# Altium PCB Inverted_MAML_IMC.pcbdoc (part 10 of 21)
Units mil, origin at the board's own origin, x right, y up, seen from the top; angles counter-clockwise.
Board outline 7677.1 x 6771.6 mil, 6 copper layers (Top Layer, Inner1, Inner2, Inner3, Inner4, Bottom Layer), stack 60.7 mil thick; 2732 components, 1531 nets, 7765 pads, 3705 vias.
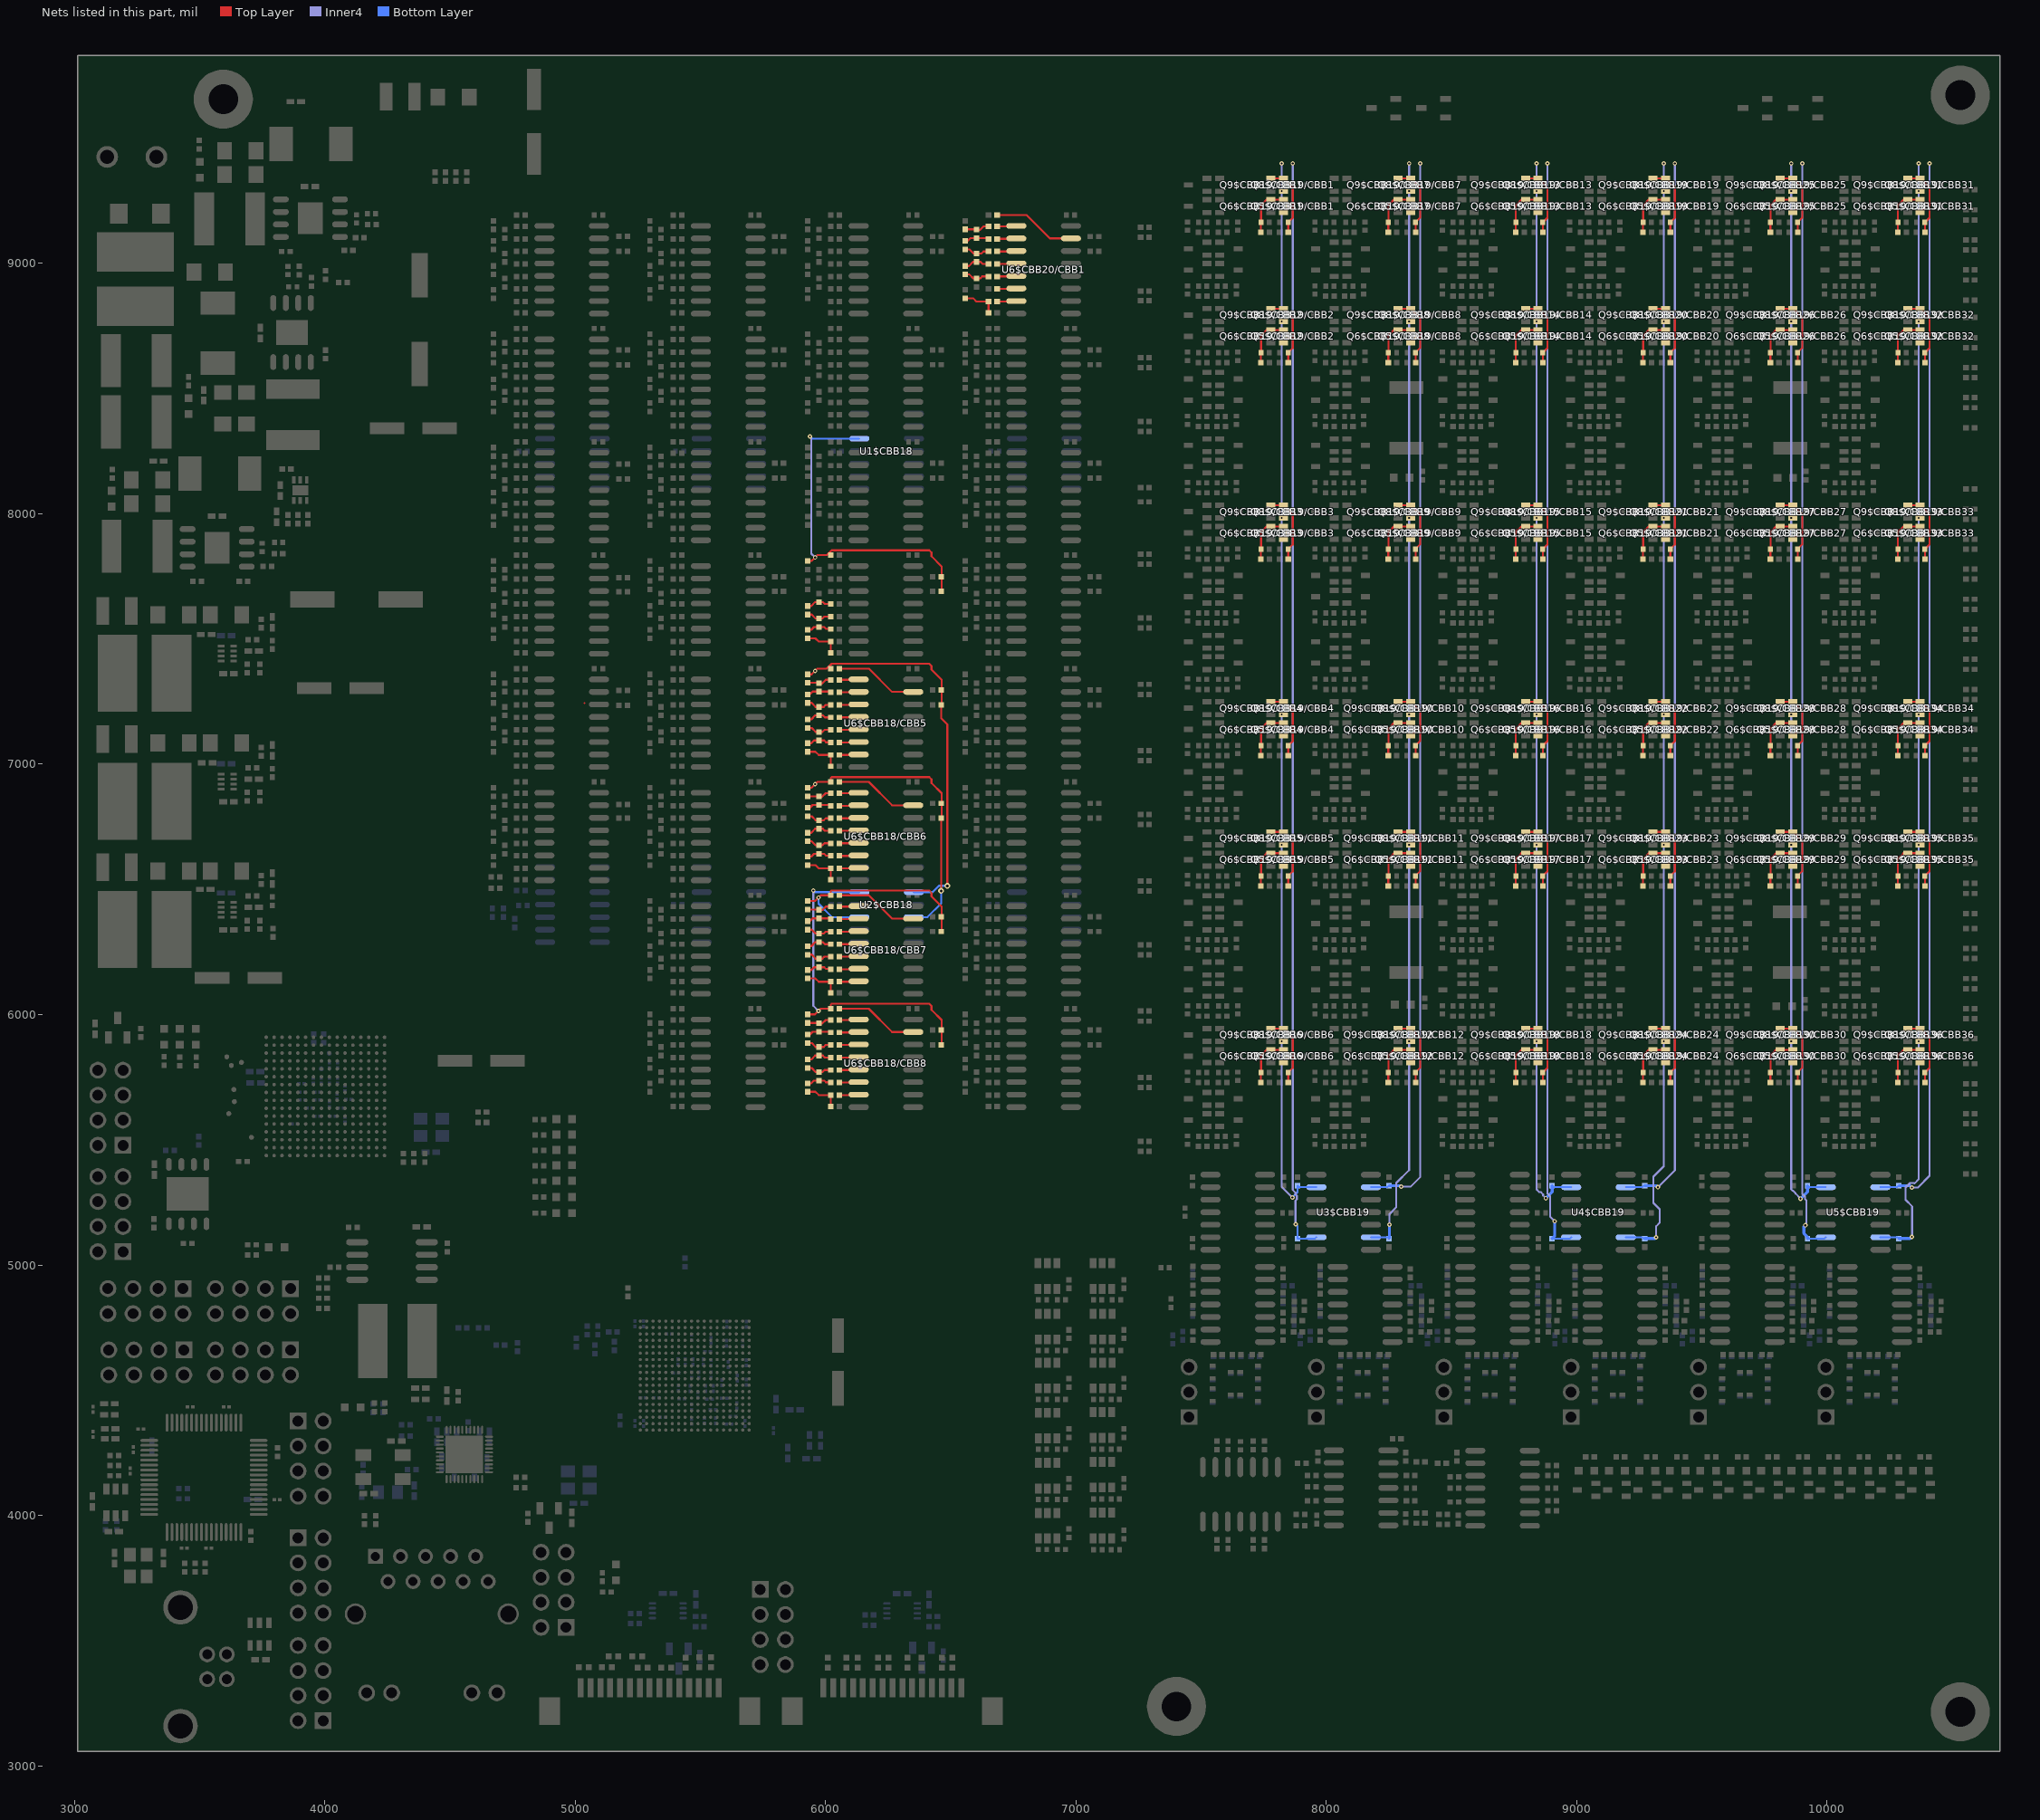
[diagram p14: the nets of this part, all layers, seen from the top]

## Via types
v1: diameter 17.7, hole 7.9, Top Layer to Bottom Layer, 3373 vias
v2: diameter 13.8, hole 7.9, Top Layer to Bottom Layer, 287 vias
v3: diameter 23.6, hole 11.8, Top Layer to Bottom Layer, 45 vias

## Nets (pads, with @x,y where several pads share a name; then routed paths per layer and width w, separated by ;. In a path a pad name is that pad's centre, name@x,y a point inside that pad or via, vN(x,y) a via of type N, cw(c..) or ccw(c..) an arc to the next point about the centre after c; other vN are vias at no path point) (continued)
$1I35\$1I23\$1N14: R4$CBB18/CBB4.2 R13$CBB18/CBB4.1 R14$CBB18/CBB4.2 | length 102.9
  Top Layer w7.9: R13$CBB18/CBB4.1@5928.7,7597.5 5945,7597.5 5960.9,7581.6 R14$CBB18/CBB4.2@5973.7,7581.6 5988.2,7581.6 5996.1,7589.6 R4$CBB18/CBB4.2@6021.7,7589.6
$1I35\$1I23\$1N15: R5$CBB18/CBB4.2 R12$CBB18/CBB4.1 R13$CBB18/CBB4.2 | length 102.8
  Top Layer w7.9: R13$CBB18/CBB4.2@5928.7,7631.6 5943.2,7631.6 5959.1,7647.5 R12$CBB18/CBB4.1@5973.7,7647.5 5990,7647.5 5998,7639.6 R5$CBB18/CBB4.2@6021.7,7639.6
$1I35\$1I23\$1N16: R1$CBB18/CBB4.2 R15$CBB18/CBB4.1 R16$CBB18/CBB4.2 | length 143.3
  Top Layer w7.9: R15$CBB18/CBB4.1@5928.7,7502.5 5960,7502.5 5973,7489.6 R1$CBB18/CBB4.2@6021.7,7489.6 R16$CBB18/CBB4.2@6021.7,7444.6
$1I35\$1I23\$1N17: R3$CBB18/CBB4.2 R14$CBB18/CBB4.1 R15$CBB18/CBB4.2 | length 100.8
  Top Layer w7.9: R15$CBB18/CBB4.2@5928.7,7536.6 5943.2,7536.6 5954.1,7547.5 R14$CBB18/CBB4.1@5973.7,7547.5 5995,7547.5 6002,7540.5 6020.8,7540.5 R3$CBB18/CBB4.2@6021.7,7539.6
$1I35\$1I23\DAC_LAD_OUT: R2$CBB18/CBB4.2 R9$CBB18/CBB4.2 R112$CBB18.1 R128$CBB18.2 U1$CBB18.12 | length 1379.4
  Top Layer w7.9: R2$CBB18/CBB4.2@5928.7,7811.6 5944.8,7811.6 v1(5958.7,7825.5) 5967.8,7834.6 6005.1,7834.6 6024.7,7854.1 6414.4,7854.1 6423.4,7845.1 6423.4,7830.1 6464.1,7789.4 R128$CBB18.2@6464.1,7690.5
  Inner4 w7.9: v1(5938.6,8308.8) 5943.5,8303.8 5943.5,7840.6 v1(5958.7,7825.5)
  Bottom Layer w7.9: v1(5938.6,8308.8) 5947.2,8300.1 U1$CBB18.12@6135.3,8300.1
$1I35\$1I33\$1N1: R9$CBB18/CBB5.1 U6$CBB18/CBB5.15 | length 333.5
  Top Layer w7.9: R9$CBB18/CBB5.1@6055.7,7381.8 6173,7381.8 6266.2,7288.6 U6$CBB18/CBB5.15@6350.6,7288.6
$1I35\$1I33\$1N2: R8$CBB18/CBB5.1 U6$CBB18/CBB5.1 | length 77.6
  Top Layer w7.9: R8$CBB18/CBB5.1@6055.7,7336.8 6130.8,7336.8 U6$CBB18/CBB5.1@6132.6,7338.6
$1I35\$1I33\$1N3: R7$CBB18/CBB5.1 U6$CBB18/CBB5.2 | length 77.6
  Top Layer w7.9: R7$CBB18/CBB5.1@6055.7,7286.8 6130.8,7286.8 U6$CBB18/CBB5.2@6132.6,7288.6
$1I35\$1I33\$1N4: R6$CBB18/CBB5.1 U6$CBB18/CBB5.3 | length 77.6
  Top Layer w7.9: R6$CBB18/CBB5.1@6055.7,7236.8 6130.8,7236.8 U6$CBB18/CBB5.3@6132.6,7238.6
$1I35\$1I33\$1N5: R5$CBB18/CBB5.1 U6$CBB18/CBB5.4 | length 77.6
  Top Layer w7.9: R5$CBB18/CBB5.1@6055.7,7186.8 6130.8,7186.8 U6$CBB18/CBB5.4@6132.6,7188.6
$1I35\$1I33\$1N6: R4$CBB18/CBB5.1 U6$CBB18/CBB5.5 | length 77.6
  Top Layer w7.9: R4$CBB18/CBB5.1@6055.7,7136.8 6130.8,7136.8 U6$CBB18/CBB5.5@6132.6,7138.6
$1I35\$1I33\$1N7: R3$CBB18/CBB5.1 U6$CBB18/CBB5.6 | length 77.6
  Top Layer w7.9: R3$CBB18/CBB5.1@6055.7,7086.8 6130.8,7086.8 U6$CBB18/CBB5.6@6132.6,7088.6
$1I35\$1I33\$1N8: R1$CBB18/CBB5.1 U6$CBB18/CBB5.7 | length 77.6
  Top Layer w7.9: R1$CBB18/CBB5.1@6055.7,7036.8 6130.8,7036.8 U6$CBB18/CBB5.7@6132.6,7038.6
$1I35\$1I33\$1N11: R2$CBB18/CBB5.1 R8$CBB18/CBB5.2 R10$CBB18/CBB5.2 | length 99.7
  Top Layer w7.9: R2$CBB18/CBB5.1@5928.7,7324.8 5972.8,7324.8 R10$CBB18/CBB5.2@5973.7,7323.8 5974.8,7322.7 5987,7322.7 6001.1,7336.8 R8$CBB18/CBB5.2@6021.7,7336.8
$1I35\$1I33\$1N12: R6$CBB18/CBB5.2 R11$CBB18/CBB5.1 R12$CBB18/CBB5.2 | length 103
  Top Layer w7.9: R11$CBB18/CBB5.1@5928.7,7244.8 5945,7244.8 5960.9,7228.8 R12$CBB18/CBB5.2@5973.7,7228.8 5993.2,7228.8 6001.1,7236.8 R6$CBB18/CBB5.2@6021.7,7236.8
$1I35\$1I33\$1N13: R7$CBB18/CBB5.2 R10$CBB18/CBB5.1 R11$CBB18/CBB5.2 | length 98.8
  Top Layer w7.9: R11$CBB18/CBB5.2@5928.7,7278.8 5938.2,7278.8 5949.1,7289.8 R10$CBB18/CBB5.1@5973.7,7289.8 6018.7,7289.8 R7$CBB18/CBB5.2@6021.7,7286.8
$1I35\$1I33\$1N14: R4$CBB18/CBB5.2 R13$CBB18/CBB5.1 R14$CBB18/CBB5.2 | length 103
  Top Layer w7.9: R13$CBB18/CBB5.1@5928.7,7144.8 5945,7144.8 5960.9,7128.8 R14$CBB18/CBB5.2@5973.7,7128.8 5988.2,7128.8 5996.1,7136.8 R4$CBB18/CBB5.2@6021.7,7136.8
$1I35\$1I33\$1N15: R5$CBB18/CBB5.2 R12$CBB18/CBB5.1 R13$CBB18/CBB5.2 | length 103
  Top Layer w7.9: R13$CBB18/CBB5.2@5928.7,7178.8 5943.2,7178.8 5959.1,7194.8 R12$CBB18/CBB5.1@5973.7,7194.8 5990,7194.8 5998,7186.8 R5$CBB18/CBB5.2@6021.7,7186.8
$1I35\$1I33\$1N16: R1$CBB18/CBB5.2 R15$CBB18/CBB5.1 R16$CBB18/CBB5.2 | length 143.4
  Top Layer w7.9: R15$CBB18/CBB5.1@5928.7,7049.8 5960,7049.8 5973,7036.8 R1$CBB18/CBB5.2@6021.7,7036.8 R16$CBB18/CBB5.2@6021.7,6991.8
$1I35\$1I33\$1N17: R3$CBB18/CBB5.2 R14$CBB18/CBB5.1 R15$CBB18/CBB5.2 | length 100.9
  Top Layer w7.9: R15$CBB18/CBB5.2@5928.7,7083.8 5943.2,7083.8 5954.1,7094.8 R14$CBB18/CBB5.1@5973.7,7094.8 5995,7094.8 6002,7087.7 6020.8,7087.7 R3$CBB18/CBB5.2@6021.7,7086.8
$1I35\$1I33\DAC_LAD_OUT: R2$CBB18/CBB5.2 R9$CBB18/CBB5.2 R129$CBB18.1 R130$CBB18.2 U2$CBB18.3 | length 1566.2
  Top Layer w7.9: R2$CBB18/CBB5.2@5928.7,7358.8 5944.8,7358.8 v1(5958.7,7372.7) 5967.8,7381.8 6005.1,7381.8 6024.7,7401.4 6414.4,7401.4 6423.4,7392.4 6423.4,7377.4 6464.1,7336.7 R130$CBB18.2@6464.1,7237.7 ; R130$CBB18.2@6461.9,7237.1 6462.1,7236.9 6462.1,7183.7 6487.1,7158.7 v3(6487.1,6513.7)
  Bottom Layer w7.9: U2$CBB18.3@6353.3,6489.1 6428.1,6489.1 6453.5,6514.5 6486.4,6514.5 v3(6487.1,6513.7)
$1I35\$1I34\$1N1: R9$CBB18/CBB6.1 U6$CBB18/CBB6.15 | length 333.5
  Top Layer w7.9: R9$CBB18/CBB6.1@6055.7,6929 6173,6929 6266.2,6835.8 U6$CBB18/CBB6.15@6350.6,6835.8
$1I35\$1I34\$1N2: R8$CBB18/CBB6.1 U6$CBB18/CBB6.1 | length 77.6
  Top Layer w7.9: R8$CBB18/CBB6.1@6055.7,6884 6130.8,6884 U6$CBB18/CBB6.1@6132.6,6885.8
$1I35\$1I34\$1N3: R7$CBB18/CBB6.1 U6$CBB18/CBB6.2 | length 77.6
  Top Layer w7.9: R7$CBB18/CBB6.1@6055.7,6834 6130.8,6834 U6$CBB18/CBB6.2@6132.6,6835.8
$1I35\$1I34\$1N4: R6$CBB18/CBB6.1 U6$CBB18/CBB6.3 | length 77.6
  Top Layer w7.9: R6$CBB18/CBB6.1@6055.7,6784 6130.8,6784 U6$CBB18/CBB6.3@6132.6,6785.8
$1I35\$1I34\$1N5: R5$CBB18/CBB6.1 U6$CBB18/CBB6.4 | length 77.6
  Top Layer w7.9: R5$CBB18/CBB6.1@6055.7,6734 6130.8,6734 U6$CBB18/CBB6.4@6132.6,6735.8
$1I35\$1I34\$1N6: R4$CBB18/CBB6.1 U6$CBB18/CBB6.5 | length 77.6
  Top Layer w7.9: R4$CBB18/CBB6.1@6055.7,6684 6130.8,6684 U6$CBB18/CBB6.5@6132.6,6685.8
$1I35\$1I34\$1N7: R3$CBB18/CBB6.1 U6$CBB18/CBB6.6 | length 77.6
  Top Layer w7.9: R3$CBB18/CBB6.1@6055.7,6634 6130.8,6634 U6$CBB18/CBB6.6@6132.6,6635.8
$1I35\$1I34\$1N8: R1$CBB18/CBB6.1 U6$CBB18/CBB6.7 | length 77.6
  Top Layer w7.9: R1$CBB18/CBB6.1@6055.7,6584 6130.8,6584 U6$CBB18/CBB6.7@6132.6,6585.8
$1I35\$1I34\$1N11: R2$CBB18/CBB6.1 R8$CBB18/CBB6.2 R10$CBB18/CBB6.2 | length 99.6
  Top Layer w7.9: R2$CBB18/CBB6.1@5928.7,6872 5972.8,6872 R10$CBB18/CBB6.2@5973.7,6871.1 5974.8,6870 5987,6870 6001.1,6884 R8$CBB18/CBB6.2@6021.7,6884
$1I35\$1I34\$1N12: R6$CBB18/CBB6.2 R11$CBB18/CBB6.1 R12$CBB18/CBB6.2 | length 102.9
  Top Layer w7.9: R11$CBB18/CBB6.1@5928.7,6792 5945,6792 5960.9,6776.1 R12$CBB18/CBB6.2@5973.7,6776.1 5993.2,6776.1 6001.1,6784 R6$CBB18/CBB6.2@6021.7,6784
$1I35\$1I34\$1N13: R7$CBB18/CBB6.2 R10$CBB18/CBB6.1 R11$CBB18/CBB6.2 | length 98.8
  Top Layer w7.9: R11$CBB18/CBB6.2@5928.7,6826.1 5938.2,6826.1 5949.1,6837 R10$CBB18/CBB6.1@5973.7,6837 6018.7,6837 R7$CBB18/CBB6.2@6021.7,6834
$1I35\$1I34\$1N14: R4$CBB18/CBB6.2 R13$CBB18/CBB6.1 R14$CBB18/CBB6.2 | length 102.9
  Top Layer w7.9: R13$CBB18/CBB6.1@5928.7,6692 5945,6692 5960.9,6676.1 R14$CBB18/CBB6.2@5973.7,6676.1 5988.2,6676.1 5996.1,6684 R4$CBB18/CBB6.2@6021.7,6684
$1I35\$1I34\$1N15: R5$CBB18/CBB6.2 R12$CBB18/CBB6.1 R13$CBB18/CBB6.2 | length 102.9
  Top Layer w7.9: R13$CBB18/CBB6.2@5928.7,6726.1 5943.2,6726.1 5959.1,6742 R12$CBB18/CBB6.1@5973.7,6742 5990,6742 5998,6734 R5$CBB18/CBB6.2@6021.7,6734
$1I35\$1I34\$1N16: R1$CBB18/CBB6.2 R15$CBB18/CBB6.1 R16$CBB18/CBB6.2 | length 143.4
  Top Layer w7.9: R15$CBB18/CBB6.1@5928.7,6597 5960,6597 5973,6584 R1$CBB18/CBB6.2@6021.7,6584 R16$CBB18/CBB6.2@6021.7,6539
$1I35\$1I34\$1N17: R3$CBB18/CBB6.2 R14$CBB18/CBB6.1 R15$CBB18/CBB6.2 | length 100.9
  Top Layer w7.9: R15$CBB18/CBB6.2@5928.7,6631.1 5943.2,6631.1 5954.1,6642 R14$CBB18/CBB6.1@5973.7,6642 5995,6642 6002,6635 6020.8,6635 R3$CBB18/CBB6.2@6021.7,6634
$1I35\$1I34\DAC_LAD_OUT: R2$CBB18/CBB6.2 R9$CBB18/CBB6.2 R131$CBB18.1 R132$CBB18.2 U2$CBB18.5 | length 1169.4
  Top Layer w7.9: R2$CBB18/CBB6.2@5928.7,6906.1 5944.8,6906.1 v1(5958.7,6920) 5967.8,6929 R9$CBB18/CBB6.2@6021.7,6929 6021.7,6945.6 6024.7,6948.6 6414.4,6948.6 6423.4,6939.6 6423.4,6924.6 6464.1,6883.9 R132$CBB18.2@6464.1,6785 ; R132$CBB18.2@6461.9,6784.4 6461.9,6493.9 v3(6462.1,6493.7)
  Bottom Layer w7.9: U2$CBB18.5@6353.3,6389.1 6407.5,6389.1 6462.1,6443.7 v3(6462.1,6493.7)
$1I35\$1I35\$1N1: R9$CBB18/CBB7.1 U6$CBB18/CBB7.15 | length 333.5
  Top Layer w7.9: R9$CBB18/CBB7.1@6055.7,6476.3 6173,6476.3 6266.2,6383.1 U6$CBB18/CBB7.15@6350.6,6383.1
$1I35\$1I35\$1N2: R8$CBB18/CBB7.1 U6$CBB18/CBB7.1 | length 77.6
  Top Layer w7.9: R8$CBB18/CBB7.1@6055.7,6431.3 6130.8,6431.3 U6$CBB18/CBB7.1@6132.6,6433.1
$1I35\$1I35\$1N3: R7$CBB18/CBB7.1 U6$CBB18/CBB7.2 | length 77.6
  Top Layer w7.9: R7$CBB18/CBB7.1@6055.7,6381.3 6130.8,6381.3 U6$CBB18/CBB7.2@6132.6,6383.1
$1I35\$1I35\$1N4: R6$CBB18/CBB7.1 U6$CBB18/CBB7.3 | length 77.6
  Top Layer w7.9: R6$CBB18/CBB7.1@6055.7,6331.3 6130.8,6331.3 U6$CBB18/CBB7.3@6132.6,6333.1
$1I35\$1I35\$1N5: R5$CBB18/CBB7.1 U6$CBB18/CBB7.4 | length 77.6
  Top Layer w7.9: R5$CBB18/CBB7.1@6055.7,6281.3 6130.8,6281.3 U6$CBB18/CBB7.4@6132.6,6283.1
$1I35\$1I35\$1N6: R4$CBB18/CBB7.1 U6$CBB18/CBB7.5 | length 77.6
  Top Layer w7.9: R4$CBB18/CBB7.1@6055.7,6231.3 6130.8,6231.3 U6$CBB18/CBB7.5@6132.6,6233.1
$1I35\$1I35\$1N7: R3$CBB18/CBB7.1 U6$CBB18/CBB7.6 | length 77.6
  Top Layer w7.9: R3$CBB18/CBB7.1@6055.7,6181.3 6130.8,6181.3 U6$CBB18/CBB7.6@6132.6,6183.1
$1I35\$1I35\$1N8: R1$CBB18/CBB7.1 U6$CBB18/CBB7.7 | length 77.6
  Top Layer w7.9: R1$CBB18/CBB7.1@6055.7,6131.3 6130.8,6131.3 U6$CBB18/CBB7.7@6132.6,6133.1
$1I35\$1I35\$1N11: R2$CBB18/CBB7.1 R8$CBB18/CBB7.2 R10$CBB18/CBB7.2 | length 99.7
  Top Layer w7.9: R2$CBB18/CBB7.1@5928.7,6419.2 5972.8,6419.2 R10$CBB18/CBB7.2@5973.7,6418.3 5974.8,6417.2 5987,6417.2 6001.1,6431.3 R8$CBB18/CBB7.2@6021.7,6431.3
$1I35\$1I35\$1N12: R6$CBB18/CBB7.2 R11$CBB18/CBB7.1 R12$CBB18/CBB7.2 | length 102.9
  Top Layer w7.9: R11$CBB18/CBB7.1@5928.7,6339.2 5945,6339.2 5960.9,6323.3 R12$CBB18/CBB7.2@5973.7,6323.3 5993.2,6323.3 6001.1,6331.3 R6$CBB18/CBB7.2@6021.7,6331.3
$1I35\$1I35\$1N13: R7$CBB18/CBB7.2 R10$CBB18/CBB7.1 R11$CBB18/CBB7.2 | length 98.7
  Top Layer w7.9: R11$CBB18/CBB7.2@5928.7,6373.3 5938.2,6373.3 5949.1,6384.2 R10$CBB18/CBB7.1@5973.7,6384.2 6018.7,6384.2 R7$CBB18/CBB7.2@6021.7,6381.3
$1I35\$1I35\$1N14: R4$CBB18/CBB7.2 R13$CBB18/CBB7.1 R14$CBB18/CBB7.2 | length 102.9
  Top Layer w7.9: R13$CBB18/CBB7.1@5928.7,6239.2 5945,6239.2 5960.9,6223.3 R14$CBB18/CBB7.2@5973.7,6223.3 5988.2,6223.3 5996.1,6231.3 R4$CBB18/CBB7.2@6021.7,6231.3
$1I35\$1I35\$1N15: R5$CBB18/CBB7.2 R12$CBB18/CBB7.1 R13$CBB18/CBB7.2 | length 102.8
  Top Layer w7.9: R13$CBB18/CBB7.2@5928.7,6273.3 5943.2,6273.3 5959.1,6289.2 R12$CBB18/CBB7.1@5973.7,6289.2 5990,6289.2 5998,6281.3 R5$CBB18/CBB7.2@6021.7,6281.3
$1I35\$1I35\$1N16: R1$CBB18/CBB7.2 R15$CBB18/CBB7.1 R16$CBB18/CBB7.2 | length 143.3
  Top Layer w7.9: R15$CBB18/CBB7.1@5928.7,6144.2 5960,6144.2 5973,6131.3 R1$CBB18/CBB7.2@6021.7,6131.3 R16$CBB18/CBB7.2@6021.7,6086.3
$1I35\$1I35\$1N17: R3$CBB18/CBB7.2 R14$CBB18/CBB7.1 R15$CBB18/CBB7.2 | length 100.8
  Top Layer w7.9: R15$CBB18/CBB7.2@5928.7,6178.3 5943.2,6178.3 5954.1,6189.2 R14$CBB18/CBB7.1@5973.7,6189.2 5995,6189.2 6002,6182.2 6020.8,6182.2 R3$CBB18/CBB7.2@6021.7,6181.3
$1I35\$1I35\DAC_LAD_OUT: R2$CBB18/CBB7.2 R9$CBB18/CBB7.2 R133$CBB18.1 R134$CBB18.2 U2$CBB18.10 | length 907.3
  Top Layer w7.9: R2$CBB18/CBB7.2@5928.7,6453.3 5958.2,6453.3 v1(5972,6467.2) 5981.1,6476.3 R9$CBB18/CBB7.2@6021.7,6476.3 6021.7,6492.8 6024.7,6495.9 6414.4,6495.9 6423.4,6486.9 6423.4,6471.9 6464.1,6431.2 R134$CBB18.2@6464.1,6332.2
  Bottom Layer w7.9: v1@5972.1,6467.2 5972.1,6442.7 6025.7,6389.1 U2$CBB18.10@6135.3,6389.1
$1I35\$1I36\$1N1: R9$CBB18/CBB8.1 U6$CBB18/CBB8.15 | length 333.5
  Top Layer w7.9: R9$CBB18/CBB8.1@6055.7,6023.5 6173,6023.5 6266.2,5930.3 U6$CBB18/CBB8.15@6350.6,5930.3
$1I35\$1I36\$1N2: R8$CBB18/CBB8.1 U6$CBB18/CBB8.1 | length 77.6
  Top Layer w7.9: R8$CBB18/CBB8.1@6055.7,5978.5 6130.8,5978.5 U6$CBB18/CBB8.1@6132.6,5980.3
$1I35\$1I36\$1N3: R7$CBB18/CBB8.1 U6$CBB18/CBB8.2 | length 77.6
  Top Layer w7.9: R7$CBB18/CBB8.1@6055.7,5928.5 6130.8,5928.5 U6$CBB18/CBB8.2@6132.6,5930.3
$1I35\$1I36\$1N4: R6$CBB18/CBB8.1 U6$CBB18/CBB8.3 | length 77.6
  Top Layer w7.9: R6$CBB18/CBB8.1@6055.7,5878.5 6130.8,5878.5 U6$CBB18/CBB8.3@6132.6,5880.3
$1I35\$1I36\$1N5: R5$CBB18/CBB8.1 U6$CBB18/CBB8.4 | length 77.6
  Top Layer w7.9: R5$CBB18/CBB8.1@6055.7,5828.5 6130.8,5828.5 U6$CBB18/CBB8.4@6132.6,5830.3
$1I35\$1I36\$1N6: R4$CBB18/CBB8.1 U6$CBB18/CBB8.5 | length 77.6
  Top Layer w7.9: R4$CBB18/CBB8.1@6055.7,5778.5 6130.8,5778.5 U6$CBB18/CBB8.5@6132.6,5780.3
$1I35\$1I36\$1N7: R3$CBB18/CBB8.1 U6$CBB18/CBB8.6 | length 77.6
  Top Layer w7.9: R3$CBB18/CBB8.1@6055.7,5728.5 6130.8,5728.5 U6$CBB18/CBB8.6@6132.6,5730.3
$1I35\$1I36\$1N8: R1$CBB18/CBB8.1 U6$CBB18/CBB8.7 | length 77.6
  Top Layer w7.9: R1$CBB18/CBB8.1@6055.7,5678.5 6130.8,5678.5 U6$CBB18/CBB8.7@6132.6,5680.3
$1I35\$1I36\$1N11: R2$CBB18/CBB8.1 R8$CBB18/CBB8.2 R10$CBB18/CBB8.2 | length 99.7
  Top Layer w7.9: R2$CBB18/CBB8.1@5928.7,5966.5 5972.8,5966.5 R10$CBB18/CBB8.2@5973.7,5965.6 5974.8,5964.4 5987,5964.4 6001.1,5978.5 R8$CBB18/CBB8.2@6021.7,5978.5
$1I35\$1I36\$1N12: R6$CBB18/CBB8.2 R11$CBB18/CBB8.1 R12$CBB18/CBB8.2 | length 102.9
  Top Layer w7.9: R11$CBB18/CBB8.1@5928.7,5886.5 5945,5886.5 5960.9,5870.6 R12$CBB18/CBB8.2@5973.7,5870.6 5993.2,5870.6 6001.1,5878.5 R6$CBB18/CBB8.2@6021.7,5878.5
$1I35\$1I36\$1N13: R7$CBB18/CBB8.2 R10$CBB18/CBB8.1 R11$CBB18/CBB8.2 | length 98.8
  Top Layer w7.9: R11$CBB18/CBB8.2@5928.7,5920.6 5938.2,5920.6 5949.1,5931.5 R10$CBB18/CBB8.1@5973.7,5931.5 6018.7,5931.5 R7$CBB18/CBB8.2@6021.7,5928.5
$1I35\$1I36\$1N14: R4$CBB18/CBB8.2 R13$CBB18/CBB8.1 R14$CBB18/CBB8.2 | length 102.9
  Top Layer w7.9: R13$CBB18/CBB8.1@5928.7,5786.5 5945,5786.5 5960.9,5770.6 R14$CBB18/CBB8.2@5973.7,5770.6 5988.2,5770.6 5996.1,5778.5 R4$CBB18/CBB8.2@6021.7,5778.5
$1I35\$1I36\$1N15: R5$CBB18/CBB8.2 R12$CBB18/CBB8.1 R13$CBB18/CBB8.2 | length 102.9
  Top Layer w7.9: R13$CBB18/CBB8.2@5928.7,5820.6 5943.2,5820.6 5959.1,5836.5 R12$CBB18/CBB8.1@5973.7,5836.5 5990,5836.5 5998,5828.5 R5$CBB18/CBB8.2@6021.7,5828.5
$1I35\$1I36\$1N16: R1$CBB18/CBB8.2 R15$CBB18/CBB8.1 R16$CBB18/CBB8.2 | length 143.4
  Top Layer w7.9: R15$CBB18/CBB8.1@5928.7,5691.5 5960,5691.5 5973,5678.5 R1$CBB18/CBB8.2@6021.7,5678.5 R16$CBB18/CBB8.2@6021.7,5633.5
$1I35\$1I36\$1N17: R3$CBB18/CBB8.2 R14$CBB18/CBB8.1 R15$CBB18/CBB8.2 | length 100.9
  Top Layer w7.9: R15$CBB18/CBB8.2@5928.7,5725.6 5943.2,5725.6 5954.1,5736.5 R14$CBB18/CBB8.1@5973.7,5736.5 5995,5736.5 6002,5729.4 6020.8,5729.4 R3$CBB18/CBB8.2@6021.7,5728.5
$1I35\$1I36\DAC_LAD_OUT: R2$CBB18/CBB8.2 R9$CBB18/CBB8.2 R135$CBB18.1 R136$CBB18.2 U2$CBB18.12 | length 1373
  Top Layer w7.9: R2$CBB18/CBB8.2@5928.7,6000.6 5958.2,6000.6 v1(5972,6014.4) 5981.1,6023.5 R9$CBB18/CBB8.2@6021.7,6023.5 6021.7,6040.1 6024.7,6043.1 6414.4,6043.1 6423.4,6034.1 6423.4,6019.1 6464.1,5978.4 R136$CBB18.2@6464.1,5879.4
  Inner4 w7.9: v1(5951.7,6495.5) 5951.7,6034.8 v1(5972,6014.4)
  Bottom Layer w7.9: v1(5951.7,6495.5) 5958.1,6489.1 U2$CBB18.12@6135.3,6489.1
$1I36\$1I263\$2N1: C1$CBB19/CBB1.2 Q5$CBB19/CBB1.1 Q6$CBB19/CBB1.2 R1$CBB19/CBB1.2 | length 207
  Top Layer w7.9: R1$CBB19/CBB1.2@7739.1,9123.7 7739.1,9163.2 C1$CBB19/CBB1.2@7739.6,9163.7 7739.6,9232.2 7761.8,9254.3 Q6$CBB19/CBB1.2@7778.6,9254.3 Q5$CBB19/CBB1.1@7828.8,9254.3
$1I36\$1I263\$2N14: C3$CBB19/CBB1.2 Q8$CBB19/CBB1.1 Q9$CBB19/CBB1.2 R2$CBB19/CBB1.2 | length 289.2
  Top Layer w7.9: Q9$CBB19/CBB1.2@7778.6,9339.3 Q8$CBB19/CBB1.1@7828.8,9339.3 7866.2,9301.9 7866.2,9182.2 C3$CBB19/CBB1.2@7847.7,9163.7 7848.2,9163.2 R2$CBB19/CBB1.2@7848.2,9123.7
$1I36\$1I265\$2N1: C1$CBB19/CBB3.2 Q5$CBB19/CBB3.1 Q6$CBB19/CBB3.2 R1$CBB19/CBB3.2 | length 207
  Top Layer w7.9: R1$CBB19/CBB3.2@7739.1,7818.7 7739.1,7858.2 C1$CBB19/CBB3.2@7739.6,7858.7 7739.6,7927.2 7761.8,7949.3 Q6$CBB19/CBB3.2@7778.6,7949.3 Q5$CBB19/CBB3.1@7828.8,7949.3
$1I36\$1I265\$2N14: C3$CBB19/CBB3.2 Q8$CBB19/CBB3.1 Q9$CBB19/CBB3.2 R2$CBB19/CBB3.2 | length 289.2
  Top Layer w7.9: Q9$CBB19/CBB3.2@7778.6,8034.3 Q8$CBB19/CBB3.1@7828.8,8034.3 7866.2,7996.9 7866.2,7877.2 C3$CBB19/CBB3.2@7847.7,7858.7 7848.2,7858.2 R2$CBB19/CBB3.2@7848.2,7818.7
$1I36\$1I267\$2N1: C1$CBB19/CBB5.2 Q5$CBB19/CBB5.1 Q6$CBB19/CBB5.2 R1$CBB19/CBB5.2 | length 207
  Top Layer w7.9: R1$CBB19/CBB5.2@7739.1,6513.7 7739.1,6553.2 C1$CBB19/CBB5.2@7739.6,6553.7 7739.6,6622.2 7761.8,6644.3 Q6$CBB19/CBB5.2@7778.6,6644.3 Q5$CBB19/CBB5.1@7828.8,6644.3
$1I36\$1I267\$2N14: C3$CBB19/CBB5.2 Q8$CBB19/CBB5.1 Q9$CBB19/CBB5.2 R2$CBB19/CBB5.2 | length 289.2
  Top Layer w7.9: Q9$CBB19/CBB5.2@7778.6,6729.3 Q8$CBB19/CBB5.1@7828.8,6729.3 7866.2,6691.9 7866.2,6572.2 C3$CBB19/CBB5.2@7847.7,6553.7 7848.2,6553.2 R2$CBB19/CBB5.2@7848.2,6513.7
$1I36\$1I269\$2N1: C1$CBB19/CBB7.2 Q5$CBB19/CBB7.1 Q6$CBB19/CBB7.2 R1$CBB19/CBB7.2 | length 207
  Top Layer w7.9: R1$CBB19/CBB7.2@8247.8,9123.7 8247.8,9163.2 C1$CBB19/CBB7.2@8248.3,9163.7 8248.3,9232.2 8270.5,9254.3 Q6$CBB19/CBB7.2@8287.3,9254.3 Q5$CBB19/CBB7.1@8337.5,9254.3
$1I36\$1I269\$2N14: C3$CBB19/CBB7.2 Q8$CBB19/CBB7.1 Q9$CBB19/CBB7.2 R2$CBB19/CBB7.2 | length 289.2
  Top Layer w7.9: Q9$CBB19/CBB7.2@8287.3,9339.3 Q8$CBB19/CBB7.1@8337.5,9339.3 8374.9,9301.9 8374.9,9182.2 C3$CBB19/CBB7.2@8356.4,9163.7 8356.9,9163.2 R2$CBB19/CBB7.2@8356.9,9123.7
$1I36\$1I270\$2N1: C1$CBB19/CBB8.2 Q5$CBB19/CBB8.1 Q6$CBB19/CBB8.2 R1$CBB19/CBB8.2 | length 207
  Top Layer w7.9: R1$CBB19/CBB8.2@8247.8,8603.7 8247.8,8643.2 C1$CBB19/CBB8.2@8248.3,8643.7 8248.3,8712.2 8270.5,8734.3 Q6$CBB19/CBB8.2@8287.3,8734.3 Q5$CBB19/CBB8.1@8337.5,8734.3
$1I36\$1I270\$2N14: C3$CBB19/CBB8.2 Q8$CBB19/CBB8.1 Q9$CBB19/CBB8.2 R2$CBB19/CBB8.2 | length 289.2
  Top Layer w7.9: Q9$CBB19/CBB8.2@8287.3,8819.3 Q8$CBB19/CBB8.1@8337.5,8819.3 8374.9,8781.9 8374.9,8662.2 C3$CBB19/CBB8.2@8356.4,8643.7 8356.9,8643.2 R2$CBB19/CBB8.2@8356.9,8603.7
$1I36\$1I271\$2N1: C1$CBB19/CBB9.2 Q5$CBB19/CBB9.1 Q6$CBB19/CBB9.2 R1$CBB19/CBB9.2 | length 207
  Top Layer w7.9: R1$CBB19/CBB9.2@8247.8,7818.7 8247.8,7858.2 C1$CBB19/CBB9.2@8248.3,7858.7 8248.3,7927.2 8270.5,7949.3 Q6$CBB19/CBB9.2@8287.3,7949.3 Q5$CBB19/CBB9.1@8337.5,7949.3
$1I36\$1I271\$2N14: C3$CBB19/CBB9.2 Q8$CBB19/CBB9.1 Q9$CBB19/CBB9.2 R2$CBB19/CBB9.2 | length 289.2
  Top Layer w7.9: Q9$CBB19/CBB9.2@8287.3,8034.3 Q8$CBB19/CBB9.1@8337.5,8034.3 8374.9,7996.9 8374.9,7877.2 C3$CBB19/CBB9.2@8356.4,7858.7 8356.9,7858.2 R2$CBB19/CBB9.2@8356.9,7818.7
$1I36\$1I272\$2N1: C1$CBB19/CBB10.2 Q5$CBB19/CBB10.1 Q6$CBB19/CBB10.2 R1$CBB19/CBB10.2 | length 207
  Top Layer w7.9: R1$CBB19/CBB10.2@8247.8,7033.7 8247.8,7073.2 C1$CBB19/CBB10.2@8248.3,7073.7 8248.3,7142.2 8270.5,7164.3 Q6$CBB19/CBB10.2@8287.3,7164.3 Q5$CBB19/CBB10.1@8337.5,7164.3
$1I36\$1I272\$2N14: C3$CBB19/CBB10.2 Q8$CBB19/CBB10.1 Q9$CBB19/CBB10.2 R2$CBB19/CBB10.2 | length 289.2
  Top Layer w7.9: Q9$CBB19/CBB10.2@8287.3,7249.3 Q8$CBB19/CBB10.1@8337.5,7249.3 8374.9,7211.9 8374.9,7092.2 C3$CBB19/CBB10.2@8356.4,7073.7 8356.9,7073.2 R2$CBB19/CBB10.2@8356.9,7033.7
$1I36\$1I273\$2N1: C1$CBB19/CBB11.2 Q5$CBB19/CBB11.1 Q6$CBB19/CBB11.2 R1$CBB19/CBB11.2 | length 207
  Top Layer w7.9: R1$CBB19/CBB11.2@8247.8,6513.7 8247.8,6553.2 C1$CBB19/CBB11.2@8248.3,6553.7 8248.3,6622.2 8270.5,6644.3 Q6$CBB19/CBB11.2@8287.3,6644.3 Q5$CBB19/CBB11.1@8337.5,6644.3
$1I36\$1I273\$2N14: C3$CBB19/CBB11.2 Q8$CBB19/CBB11.1 Q9$CBB19/CBB11.2 R2$CBB19/CBB11.2 | length 289.2
  Top Layer w7.9: Q9$CBB19/CBB11.2@8287.3,6729.3 Q8$CBB19/CBB11.1@8337.5,6729.3 8374.9,6691.9 8374.9,6572.2 C3$CBB19/CBB11.2@8356.4,6553.7 8356.9,6553.2 R2$CBB19/CBB11.2@8356.9,6513.7
$1I36\$1I274\$2N1: C1$CBB19/CBB12.2 Q5$CBB19/CBB12.1 Q6$CBB19/CBB12.2 R1$CBB19/CBB12.2 | length 207
  Top Layer w7.9: R1$CBB19/CBB12.2@8247.8,5728.7 8247.8,5768.2 C1$CBB19/CBB12.2@8248.3,5768.7 8248.3,5837.2 8270.5,5859.3 Q6$CBB19/CBB12.2@8287.3,5859.3 Q5$CBB19/CBB12.1@8337.5,5859.3
$1I36\$1I274\$2N14: C3$CBB19/CBB12.2 Q8$CBB19/CBB12.1 Q9$CBB19/CBB12.2 R2$CBB19/CBB12.2 | length 289.2
  Top Layer w7.9: Q9$CBB19/CBB12.2@8287.3,5944.3 Q8$CBB19/CBB12.1@8337.5,5944.3 8374.9,5906.9 8374.9,5787.2 C3$CBB19/CBB12.2@8356.4,5768.7 8356.9,5768.2 R2$CBB19/CBB12.2@8356.9,5728.7
$1I36\$1I275\$2N1: C1$CBB19/CBB13.2 Q5$CBB19/CBB13.1 Q6$CBB19/CBB13.2 R1$CBB19/CBB13.2 | length 207
  Top Layer w7.9: R1$CBB19/CBB13.2@8756.5,9123.7 8756.5,9163.2 C1$CBB19/CBB13.2@8757,9163.7 8757,9232.2 8779.2,9254.3 Q6$CBB19/CBB13.2@8796,9254.3 Q5$CBB19/CBB13.1@8846.2,9254.3
$1I36\$1I275\$2N14: C3$CBB19/CBB13.2 Q8$CBB19/CBB13.1 Q9$CBB19/CBB13.2 R2$CBB19/CBB13.2 | length 289.2
  Top Layer w7.9: Q9$CBB19/CBB13.2@8796,9339.3 Q8$CBB19/CBB13.1@8846.2,9339.3 8883.6,9301.9 8883.6,9182.2 C3$CBB19/CBB13.2@8865.1,9163.7 8865.6,9163.2 R2$CBB19/CBB13.2@8865.6,9123.7
$1I36\$1I276\$2N1: C1$CBB19/CBB14.2 Q5$CBB19/CBB14.1 Q6$CBB19/CBB14.2 R1$CBB19/CBB14.2 | length 207
  Top Layer w7.9: R1$CBB19/CBB14.2@8756.5,8603.7 8756.5,8643.2 C1$CBB19/CBB14.2@8757,8643.7 8757,8712.2 8779.2,8734.3 Q6$CBB19/CBB14.2@8796,8734.3 Q5$CBB19/CBB14.1@8846.2,8734.3
$1I36\$1I276\$2N14: C3$CBB19/CBB14.2 Q8$CBB19/CBB14.1 Q9$CBB19/CBB14.2 R2$CBB19/CBB14.2 | length 289.2
  Top Layer w7.9: Q9$CBB19/CBB14.2@8796,8819.3 Q8$CBB19/CBB14.1@8846.2,8819.3 8883.6,8781.9 8883.6,8662.2 C3$CBB19/CBB14.2@8865.1,8643.7 8865.6,8643.2 R2$CBB19/CBB14.2@8865.6,8603.7
$1I36\$1I277\$2N1: C1$CBB19/CBB15.2 Q5$CBB19/CBB15.1 Q6$CBB19/CBB15.2 R1$CBB19/CBB15.2 | length 207
  Top Layer w7.9: R1$CBB19/CBB15.2@8756.5,7818.7 8756.5,7858.2 C1$CBB19/CBB15.2@8757,7858.7 8757,7927.2 8779.2,7949.3 Q6$CBB19/CBB15.2@8796,7949.3 Q5$CBB19/CBB15.1@8846.2,7949.3
$1I36\$1I277\$2N14: C3$CBB19/CBB15.2 Q8$CBB19/CBB15.1 Q9$CBB19/CBB15.2 R2$CBB19/CBB15.2 | length 289.2
  Top Layer w7.9: Q9$CBB19/CBB15.2@8796,8034.3 Q8$CBB19/CBB15.1@8846.2,8034.3 8883.6,7996.9 8883.6,7877.2 C3$CBB19/CBB15.2@8865.1,7858.7 8865.6,7858.2 R2$CBB19/CBB15.2@8865.6,7818.7
$1I36\$1I278\$2N1: C1$CBB19/CBB16.2 Q5$CBB19/CBB16.1 Q6$CBB19/CBB16.2 R1$CBB19/CBB16.2 | length 207
  Top Layer w7.9: R1$CBB19/CBB16.2@8756.5,7033.7 8756.5,7073.2 C1$CBB19/CBB16.2@8757,7073.7 8757,7142.2 8779.2,7164.3 Q6$CBB19/CBB16.2@8796,7164.3 Q5$CBB19/CBB16.1@8846.2,7164.3
$1I36\$1I278\$2N14: C3$CBB19/CBB16.2 Q8$CBB19/CBB16.1 Q9$CBB19/CBB16.2 R2$CBB19/CBB16.2 | length 289.2
  Top Layer w7.9: Q9$CBB19/CBB16.2@8796,7249.3 Q8$CBB19/CBB16.1@8846.2,7249.3 8883.6,7211.9 8883.6,7092.2 C3$CBB19/CBB16.2@8865.1,7073.7 8865.6,7073.2 R2$CBB19/CBB16.2@8865.6,7033.7
$1I36\$1I279\$2N1: C1$CBB19/CBB17.2 Q5$CBB19/CBB17.1 Q6$CBB19/CBB17.2 R1$CBB19/CBB17.2 | length 207
  Top Layer w7.9: R1$CBB19/CBB17.2@8756.5,6513.7 8756.5,6553.2 C1$CBB19/CBB17.2@8757,6553.7 8757,6622.2 8779.2,6644.3 Q6$CBB19/CBB17.2@8796,6644.3 Q5$CBB19/CBB17.1@8846.2,6644.3
$1I36\$1I279\$2N14: C3$CBB19/CBB17.2 Q8$CBB19/CBB17.1 Q9$CBB19/CBB17.2 R2$CBB19/CBB17.2 | length 289.2
  Top Layer w7.9: Q9$CBB19/CBB17.2@8796,6729.3 Q8$CBB19/CBB17.1@8846.2,6729.3 8883.6,6691.9 8883.6,6572.2 C3$CBB19/CBB17.2@8865.1,6553.7 8865.6,6553.2 R2$CBB19/CBB17.2@8865.6,6513.7
$1I36\$1I280\$2N1: C1$CBB19/CBB18.2 Q5$CBB19/CBB18.1 Q6$CBB19/CBB18.2 R1$CBB19/CBB18.2 | length 207
  Top Layer w7.9: R1$CBB19/CBB18.2@8756.5,5728.7 8756.5,5768.2 C1$CBB19/CBB18.2@8757,5768.7 8757,5837.2 8779.2,5859.3 Q6$CBB19/CBB18.2@8796,5859.3 Q5$CBB19/CBB18.1@8846.2,5859.3
$1I36\$1I280\$2N14: C3$CBB19/CBB18.2 Q8$CBB19/CBB18.1 Q9$CBB19/CBB18.2 R2$CBB19/CBB18.2 | length 289.2
  Top Layer w7.9: Q9$CBB19/CBB18.2@8796,5944.3 Q8$CBB19/CBB18.1@8846.2,5944.3 8883.6,5906.9 8883.6,5787.2 C3$CBB19/CBB18.2@8865.1,5768.7 8865.6,5768.2 R2$CBB19/CBB18.2@8865.6,5728.7
$1I36\$1I287\$2N1: C1$CBB19/CBB19.2 Q5$CBB19/CBB19.1 Q6$CBB19/CBB19.2 R1$CBB19/CBB19.2 | length 207
  Top Layer w7.9: R1$CBB19/CBB19.2@9265.2,9123.7 9265.2,9163.2 C1$CBB19/CBB19.2@9265.7,9163.7 9265.7,9232.2 9287.9,9254.3 Q6$CBB19/CBB19.2@9304.7,9254.3 Q5$CBB19/CBB19.1@9354.9,9254.3
$1I36\$1I287\$2N14: C3$CBB19/CBB19.2 Q8$CBB19/CBB19.1 Q9$CBB19/CBB19.2 R2$CBB19/CBB19.2 | length 289.2
  Top Layer w7.9: Q9$CBB19/CBB19.2@9304.7,9339.3 Q8$CBB19/CBB19.1@9354.9,9339.3 9392.3,9301.9 9392.3,9182.2 C3$CBB19/CBB19.2@9373.8,9163.7 9374.3,9163.2 R2$CBB19/CBB19.2@9374.3,9123.7
$1I36\$1I288\$2N1: C1$CBB19/CBB20.2 Q5$CBB19/CBB20.1 Q6$CBB19/CBB20.2 R1$CBB19/CBB20.2 | length 207
  Top Layer w7.9: R1$CBB19/CBB20.2@9265.2,8603.7 9265.2,8643.2 C1$CBB19/CBB20.2@9265.7,8643.7 9265.7,8712.2 9287.9,8734.3 Q6$CBB19/CBB20.2@9304.7,8734.3 Q5$CBB19/CBB20.1@9354.9,8734.3
$1I36\$1I288\$2N14: C3$CBB19/CBB20.2 Q8$CBB19/CBB20.1 Q9$CBB19/CBB20.2 R2$CBB19/CBB20.2 | length 289.2
  Top Layer w7.9: Q9$CBB19/CBB20.2@9304.7,8819.3 Q8$CBB19/CBB20.1@9354.9,8819.3 9392.3,8781.9 9392.3,8662.2 C3$CBB19/CBB20.2@9373.8,8643.7 9374.3,8643.2 R2$CBB19/CBB20.2@9374.3,8603.7
$1I36\$1I289\$2N1: C1$CBB19/CBB21.2 Q5$CBB19/CBB21.1 Q6$CBB19/CBB21.2 R1$CBB19/CBB21.2 | length 207
  Top Layer w7.9: R1$CBB19/CBB21.2@9265.2,7818.7 9265.2,7858.2 C1$CBB19/CBB21.2@9265.7,7858.7 9265.7,7927.2 9287.9,7949.3 Q6$CBB19/CBB21.2@9304.7,7949.3 Q5$CBB19/CBB21.1@9354.9,7949.3
$1I36\$1I289\$2N14: C3$CBB19/CBB21.2 Q8$CBB19/CBB21.1 Q9$CBB19/CBB21.2 R2$CBB19/CBB21.2 | length 289.2
  Top Layer w7.9: Q9$CBB19/CBB21.2@9304.7,8034.3 Q8$CBB19/CBB21.1@9354.9,8034.3 9392.3,7996.9 9392.3,7877.2 C3$CBB19/CBB21.2@9373.8,7858.7 9374.3,7858.2 R2$CBB19/CBB21.2@9374.3,7818.7
$1I36\$1I290\$2N1: C1$CBB19/CBB22.2 Q5$CBB19/CBB22.1 Q6$CBB19/CBB22.2 R1$CBB19/CBB22.2 | length 207
  Top Layer w7.9: R1$CBB19/CBB22.2@9265.2,7033.7 9265.2,7073.2 C1$CBB19/CBB22.2@9265.7,7073.7 9265.7,7142.2 9287.9,7164.3 Q6$CBB19/CBB22.2@9304.7,7164.3 Q5$CBB19/CBB22.1@9354.9,7164.3
$1I36\$1I290\$2N14: C3$CBB19/CBB22.2 Q8$CBB19/CBB22.1 Q9$CBB19/CBB22.2 R2$CBB19/CBB22.2 | length 289.2
  Top Layer w7.9: Q9$CBB19/CBB22.2@9304.7,7249.3 Q8$CBB19/CBB22.1@9354.9,7249.3 9392.3,7211.9 9392.3,7092.2 C3$CBB19/CBB22.2@9373.8,7073.7 9374.3,7073.2 R2$CBB19/CBB22.2@9374.3,7033.7
$1I36\$1I291\$2N1: C1$CBB19/CBB23.2 Q5$CBB19/CBB23.1 Q6$CBB19/CBB23.2 R1$CBB19/CBB23.2 | length 207
  Top Layer w7.9: R1$CBB19/CBB23.2@9265.2,6513.7 9265.2,6553.2 C1$CBB19/CBB23.2@9265.7,6553.7 9265.7,6622.2 9287.9,6644.3 Q6$CBB19/CBB23.2@9304.7,6644.3 Q5$CBB19/CBB23.1@9354.9,6644.3
$1I36\$1I291\$2N14: C3$CBB19/CBB23.2 Q8$CBB19/CBB23.1 Q9$CBB19/CBB23.2 R2$CBB19/CBB23.2 | length 289.2
  Top Layer w7.9: Q9$CBB19/CBB23.2@9304.7,6729.3 Q8$CBB19/CBB23.1@9354.9,6729.3 9392.3,6691.9 9392.3,6572.2 C3$CBB19/CBB23.2@9373.8,6553.7 9374.3,6553.2 R2$CBB19/CBB23.2@9374.3,6513.7
$1I36\$1I292\$2N1: C1$CBB19/CBB24.2 Q5$CBB19/CBB24.1 Q6$CBB19/CBB24.2 R1$CBB19/CBB24.2 | length 207
  Top Layer w7.9: R1$CBB19/CBB24.2@9265.2,5728.7 9265.2,5768.2 C1$CBB19/CBB24.2@9265.7,5768.7 9265.7,5837.2 9287.9,5859.3 Q6$CBB19/CBB24.2@9304.7,5859.3 Q5$CBB19/CBB24.1@9354.9,5859.3
$1I36\$1I292\$2N14: C3$CBB19/CBB24.2 Q8$CBB19/CBB24.1 Q9$CBB19/CBB24.2 R2$CBB19/CBB24.2 | length 289.2
  Top Layer w7.9: Q9$CBB19/CBB24.2@9304.7,5944.3 Q8$CBB19/CBB24.1@9354.9,5944.3 9392.3,5906.9 9392.3,5787.2 C3$CBB19/CBB24.2@9373.8,5768.7 9374.3,5768.2 R2$CBB19/CBB24.2@9374.3,5728.7
$1I36\$1I293\$2N1: C1$CBB19/CBB25.2 Q5$CBB19/CBB25.1 Q6$CBB19/CBB25.2 R1$CBB19/CBB25.2 | length 207
  Top Layer w7.9: R1$CBB19/CBB25.2@9773.9,9123.7 9773.9,9163.2 C1$CBB19/CBB25.2@9774.4,9163.7 9774.4,9232.2 9796.6,9254.3 Q6$CBB19/CBB25.2@9813.4,9254.3 Q5$CBB19/CBB25.1@9863.6,9254.3
$1I36\$1I293\$2N14: C3$CBB19/CBB25.2 Q8$CBB19/CBB25.1 Q9$CBB19/CBB25.2 R2$CBB19/CBB25.2 | length 289.2
  Top Layer w7.9: Q9$CBB19/CBB25.2@9813.4,9339.3 Q8$CBB19/CBB25.1@9863.6,9339.3 9901,9301.9 9901,9182.2 C3$CBB19/CBB25.2@9882.5,9163.7 9883,9163.2 R2$CBB19/CBB25.2@9883,9123.7
$1I36\$1I294\$2N1: C1$CBB19/CBB26.2 Q5$CBB19/CBB26.1 Q6$CBB19/CBB26.2 R1$CBB19/CBB26.2 | length 207
  Top Layer w7.9: R1$CBB19/CBB26.2@9773.9,8603.7 9773.9,8643.2 C1$CBB19/CBB26.2@9774.4,8643.7 9774.4,8712.2 9796.6,8734.3 Q6$CBB19/CBB26.2@9813.4,8734.3 Q5$CBB19/CBB26.1@9863.6,8734.3
$1I36\$1I294\$2N14: C3$CBB19/CBB26.2 Q8$CBB19/CBB26.1 Q9$CBB19/CBB26.2 R2$CBB19/CBB26.2 | length 289.2
  Top Layer w7.9: Q9$CBB19/CBB26.2@9813.4,8819.3 Q8$CBB19/CBB26.1@9863.6,8819.3 9901,8781.9 9901,8662.2 C3$CBB19/CBB26.2@9882.5,8643.7 9883,8643.2 R2$CBB19/CBB26.2@9883,8603.7
$1I36\$1I295\$2N1: C1$CBB19/CBB27.2 Q5$CBB19/CBB27.1 Q6$CBB19/CBB27.2 R1$CBB19/CBB27.2 | length 207
  Top Layer w7.9: R1$CBB19/CBB27.2@9773.9,7818.7 9773.9,7858.2 C1$CBB19/CBB27.2@9774.4,7858.7 9774.4,7927.2 9796.6,7949.3 Q6$CBB19/CBB27.2@9813.4,7949.3 Q5$CBB19/CBB27.1@9863.6,7949.3
$1I36\$1I295\$2N14: C3$CBB19/CBB27.2 Q8$CBB19/CBB27.1 Q9$CBB19/CBB27.2 R2$CBB19/CBB27.2 | length 289.2
  Top Layer w7.9: Q9$CBB19/CBB27.2@9813.4,8034.3 Q8$CBB19/CBB27.1@9863.6,8034.3 9901,7996.9 9901,7877.2 C3$CBB19/CBB27.2@9882.5,7858.7 9883,7858.2 R2$CBB19/CBB27.2@9883,7818.7
$1I36\$1I296\$2N1: C1$CBB19/CBB28.2 Q5$CBB19/CBB28.1 Q6$CBB19/CBB28.2 R1$CBB19/CBB28.2 | length 207
  Top Layer w7.9: R1$CBB19/CBB28.2@9773.9,7033.7 9773.9,7073.2 C1$CBB19/CBB28.2@9774.4,7073.7 9774.4,7142.2 9796.6,7164.3 Q6$CBB19/CBB28.2@9813.4,7164.3 Q5$CBB19/CBB28.1@9863.6,7164.3
$1I36\$1I296\$2N14: C3$CBB19/CBB28.2 Q8$CBB19/CBB28.1 Q9$CBB19/CBB28.2 R2$CBB19/CBB28.2 | length 289.2
  Top Layer w7.9: Q9$CBB19/CBB28.2@9813.4,7249.3 Q8$CBB19/CBB28.1@9863.6,7249.3 9901,7211.9 9901,7092.2 C3$CBB19/CBB28.2@9882.5,7073.7 9883,7073.2 R2$CBB19/CBB28.2@9883,7033.7
$1I36\$1I297\$2N1: C1$CBB19/CBB29.2 Q5$CBB19/CBB29.1 Q6$CBB19/CBB29.2 R1$CBB19/CBB29.2 | length 207
  Top Layer w7.9: R1$CBB19/CBB29.2@9773.9,6513.7 9773.9,6553.2 C1$CBB19/CBB29.2@9774.4,6553.7 9774.4,6622.2 9796.6,6644.3 Q6$CBB19/CBB29.2@9813.4,6644.3 Q5$CBB19/CBB29.1@9863.6,6644.3
$1I36\$1I297\$2N14: C3$CBB19/CBB29.2 Q8$CBB19/CBB29.1 Q9$CBB19/CBB29.2 R2$CBB19/CBB29.2 | length 289.2
  Top Layer w7.9: Q9$CBB19/CBB29.2@9813.4,6729.3 Q8$CBB19/CBB29.1@9863.6,6729.3 9901,6691.9 9901,6572.2 C3$CBB19/CBB29.2@9882.5,6553.7 9883,6553.2 R2$CBB19/CBB29.2@9883,6513.7
$1I36\$1I298\$2N1: C1$CBB19/CBB30.2 Q5$CBB19/CBB30.1 Q6$CBB19/CBB30.2 R1$CBB19/CBB30.2 | length 207
  Top Layer w7.9: R1$CBB19/CBB30.2@9773.9,5728.7 9773.9,5768.2 C1$CBB19/CBB30.2@9774.4,5768.7 9774.4,5837.2 9796.6,5859.3 Q6$CBB19/CBB30.2@9813.4,5859.3 Q5$CBB19/CBB30.1@9863.6,5859.3
$1I36\$1I298\$2N14: C3$CBB19/CBB30.2 Q8$CBB19/CBB30.1 Q9$CBB19/CBB30.2 R2$CBB19/CBB30.2 | length 289.2
  Top Layer w7.9: Q9$CBB19/CBB30.2@9813.4,5944.3 Q8$CBB19/CBB30.1@9863.6,5944.3 9901,5906.9 9901,5787.2 C3$CBB19/CBB30.2@9882.5,5768.7 9883,5768.2 R2$CBB19/CBB30.2@9883,5728.7
$1I36\$1I299\$2N1: C1$CBB19/CBB31.2 Q5$CBB19/CBB31.1 Q6$CBB19/CBB31.2 R1$CBB19/CBB31.2 | length 207
  Top Layer w7.9: R1$CBB19/CBB31.2@10282.6,9123.7 10282.6,9163.2 C1$CBB19/CBB31.2@10283.1,9163.7 10283.1,9232.2 10305.3,9254.3 Q6$CBB19/CBB31.2@10322.1,9254.3 Q5$CBB19/CBB31.1@10372.3,9254.3
$1I36\$1I299\$2N14: C3$CBB19/CBB31.2 Q8$CBB19/CBB31.1 Q9$CBB19/CBB31.2 R2$CBB19/CBB31.2 | length 289.2
  Top Layer w7.9: Q9$CBB19/CBB31.2@10322.1,9339.3 Q8$CBB19/CBB31.1@10372.3,9339.3 10409.7,9301.9 10409.7,9182.2 C3$CBB19/CBB31.2@10391.2,9163.7 10391.7,9163.2 R2$CBB19/CBB31.2@10391.7,9123.7
$1I36\$1I300\$2N1: C1$CBB19/CBB32.2 Q5$CBB19/CBB32.1 Q6$CBB19/CBB32.2 R1$CBB19/CBB32.2 | length 207
  Top Layer w7.9: R1$CBB19/CBB32.2@10282.6,8603.7 10282.6,8643.2 C1$CBB19/CBB32.2@10283.1,8643.7 10283.1,8712.2 10305.3,8734.3 Q6$CBB19/CBB32.2@10322.1,8734.3 Q5$CBB19/CBB32.1@10372.3,8734.3
$1I36\$1I300\$2N14: C3$CBB19/CBB32.2 Q8$CBB19/CBB32.1 Q9$CBB19/CBB32.2 R2$CBB19/CBB32.2 | length 289.2
  Top Layer w7.9: Q9$CBB19/CBB32.2@10322.1,8819.3 Q8$CBB19/CBB32.1@10372.3,8819.3 10409.7,8781.9 10409.7,8662.2 C3$CBB19/CBB32.2@10391.2,8643.7 10391.7,8643.2 R2$CBB19/CBB32.2@10391.7,8603.7
$1I36\$1I301\$2N1: C1$CBB19/CBB33.2 Q5$CBB19/CBB33.1 Q6$CBB19/CBB33.2 R1$CBB19/CBB33.2 | length 207
  Top Layer w7.9: R1$CBB19/CBB33.2@10282.6,7818.7 10282.6,7858.2 C1$CBB19/CBB33.2@10283.1,7858.7 10283.1,7927.2 10305.3,7949.3 Q6$CBB19/CBB33.2@10322.1,7949.3 Q5$CBB19/CBB33.1@10372.3,7949.3
$1I36\$1I301\$2N14: C3$CBB19/CBB33.2 Q8$CBB19/CBB33.1 Q9$CBB19/CBB33.2 R2$CBB19/CBB33.2 | length 289.2
  Top Layer w7.9: Q9$CBB19/CBB33.2@10322.1,8034.3 Q8$CBB19/CBB33.1@10372.3,8034.3 10409.7,7996.9 10409.7,7877.2 C3$CBB19/CBB33.2@10391.2,7858.7 10391.7,7858.2 R2$CBB19/CBB33.2@10391.7,7818.7
$1I36\$1I302\$2N1: C1$CBB19/CBB34.2 Q5$CBB19/CBB34.1 Q6$CBB19/CBB34.2 R1$CBB19/CBB34.2 | length 207
  Top Layer w7.9: R1$CBB19/CBB34.2@10282.6,7033.7 10282.6,7073.2 C1$CBB19/CBB34.2@10283.1,7073.7 10283.1,7142.2 10305.3,7164.3 Q6$CBB19/CBB34.2@10322.1,7164.3 Q5$CBB19/CBB34.1@10372.3,7164.3
$1I36\$1I302\$2N14: C3$CBB19/CBB34.2 Q8$CBB19/CBB34.1 Q9$CBB19/CBB34.2 R2$CBB19/CBB34.2 | length 289.2
  Top Layer w7.9: Q9$CBB19/CBB34.2@10322.1,7249.3 Q8$CBB19/CBB34.1@10372.3,7249.3 10409.7,7211.9 10409.7,7092.2 C3$CBB19/CBB34.2@10391.2,7073.7 10391.7,7073.2 R2$CBB19/CBB34.2@10391.7,7033.7
$1I36\$1I303\$2N1: C1$CBB19/CBB35.2 Q5$CBB19/CBB35.1 Q6$CBB19/CBB35.2 R1$CBB19/CBB35.2 | length 207
  Top Layer w7.9: R1$CBB19/CBB35.2@10282.6,6513.7 10282.6,6553.2 C1$CBB19/CBB35.2@10283.1,6553.7 10283.1,6622.2 10305.3,6644.3 Q6$CBB19/CBB35.2@10322.1,6644.3 Q5$CBB19/CBB35.1@10372.3,6644.3
$1I36\$1I303\$2N14: C3$CBB19/CBB35.2 Q8$CBB19/CBB35.1 Q9$CBB19/CBB35.2 R2$CBB19/CBB35.2 | length 289.2
  Top Layer w7.9: Q9$CBB19/CBB35.2@10322.1,6729.3 Q8$CBB19/CBB35.1@10372.3,6729.3 10409.7,6691.9 10409.7,6572.2 C3$CBB19/CBB35.2@10391.2,6553.7 10391.7,6553.2 R2$CBB19/CBB35.2@10391.7,6513.7
$1I36\$1I304\$2N1: C1$CBB19/CBB36.2 Q5$CBB19/CBB36.1 Q6$CBB19/CBB36.2 R1$CBB19/CBB36.2 | length 207
  Top Layer w7.9: R1$CBB19/CBB36.2@10282.6,5728.7 10282.6,5768.2 C1$CBB19/CBB36.2@10283.1,5768.7 10283.1,5837.2 10305.3,5859.3 Q6$CBB19/CBB36.2@10322.1,5859.3 Q5$CBB19/CBB36.1@10372.3,5859.3
$1I36\$1I304\$2N14: C3$CBB19/CBB36.2 Q8$CBB19/CBB36.1 Q9$CBB19/CBB36.2 R2$CBB19/CBB36.2 | length 289.2
  Top Layer w7.9: Q9$CBB19/CBB36.2@10322.1,5944.3 Q8$CBB19/CBB36.1@10372.3,5944.3 10409.7,5906.9 10409.7,5787.2 C3$CBB19/CBB36.2@10391.2,5768.7 10391.7,5768.2 R2$CBB19/CBB36.2@10391.7,5728.7
$1I36\$1I317\$2N1: C1$CBB19/CBB2.2 Q5$CBB19/CBB2.1 Q6$CBB19/CBB2.2 R1$CBB19/CBB2.2 | length 207
  Top Layer w7.9: R1$CBB19/CBB2.2@7739.1,8603.7 7739.1,8643.2 C1$CBB19/CBB2.2@7739.6,8643.7 7739.6,8712.2 7761.8,8734.3 Q6$CBB19/CBB2.2@7778.6,8734.3 Q5$CBB19/CBB2.1@7828.8,8734.3
$1I36\$1I317\$2N14: C3$CBB19/CBB2.2 Q8$CBB19/CBB2.1 Q9$CBB19/CBB2.2 R2$CBB19/CBB2.2 | length 289.2
  Top Layer w7.9: Q9$CBB19/CBB2.2@7778.6,8819.3 Q8$CBB19/CBB2.1@7828.8,8819.3 7866.2,8781.9 7866.2,8662.2 C3$CBB19/CBB2.2@7847.7,8643.7 7848.2,8643.2 R2$CBB19/CBB2.2@7848.2,8603.7
$1I36\$1I318\$2N1: C1$CBB19/CBB4.2 Q5$CBB19/CBB4.1 Q6$CBB19/CBB4.2 R1$CBB19/CBB4.2 | length 207
  Top Layer w7.9: R1$CBB19/CBB4.2@7739.1,7033.7 7739.1,7073.2 C1$CBB19/CBB4.2@7739.6,7073.7 7739.6,7142.2 7761.8,7164.3 Q6$CBB19/CBB4.2@7778.6,7164.3 Q5$CBB19/CBB4.1@7828.8,7164.3
$1I36\$1I318\$2N14: C3$CBB19/CBB4.2 Q8$CBB19/CBB4.1 Q9$CBB19/CBB4.2 R2$CBB19/CBB4.2 | length 289.2
  Top Layer w7.9: Q9$CBB19/CBB4.2@7778.6,7249.3 Q8$CBB19/CBB4.1@7828.8,7249.3 7866.2,7211.9 7866.2,7092.2 C3$CBB19/CBB4.2@7847.7,7073.7 7848.2,7073.2 R2$CBB19/CBB4.2@7848.2,7033.7
$1I36\$1I319\$2N1: C1$CBB19/CBB6.2 Q5$CBB19/CBB6.1 Q6$CBB19/CBB6.2 R1$CBB19/CBB6.2 | length 207
  Top Layer w7.9: R1$CBB19/CBB6.2@7739.1,5728.7 7739.1,5768.2 C1$CBB19/CBB6.2@7739.6,5768.7 7739.6,5837.2 7761.8,5859.3 Q6$CBB19/CBB6.2@7778.6,5859.3 Q5$CBB19/CBB6.1@7828.8,5859.3
$1I36\$1I319\$2N14: C3$CBB19/CBB6.2 Q8$CBB19/CBB6.1 Q9$CBB19/CBB6.2 R2$CBB19/CBB6.2 | length 289.2
  Top Layer w7.9: Q9$CBB19/CBB6.2@7778.6,5944.3 Q8$CBB19/CBB6.1@7828.8,5944.3 7866.2,5906.9 7866.2,5787.2 C3$CBB19/CBB6.2@7847.7,5768.7 7848.2,5768.2 R2$CBB19/CBB6.2@7848.2,5728.7
$1I36\COL+1: Q5$CBB19/CBB1.2 Q5$CBB19/CBB2.2 Q5$CBB19/CBB3.2 Q5$CBB19/CBB4.2 Q5$CBB19/CBB5.2 Q5$CBB19/CBB6.2 R3$CBB19.2 U3$CBB19.2 | length 4699.5
  Top Layer w7.9: Q5$CBB19/CBB6.2@7828.8,5808.2 7846.2,5825.6 v1(7846.2,5833.7) ; Q5$CBB19/CBB5.2@7828.8,6593.2 7846.2,6610.6 v1(7846.2,6618.7) ; Q5$CBB19/CBB4.2@7828.8,7113.2 7846.2,7130.6 v1(7846.2,7138.7) ; Q5$CBB19/CBB3.2@7828.8,7898.2 7846.2,7915.6 v1(7846.2,7923.7) ; Q5$CBB19/CBB2.2@7828.8,8683.2 7846.2,8700.6 v1(7846.2,8708.7) ; Q5$CBB19/CBB1.2@7828.8,9203.2 7846.2,9220.6 v1(7846.2,9228.7)
  Inner4 w7.9: v1(7846.2,5833.7) 7866.2,5833.7 ; v1(7846.2,6618.7) 7866.2,6618.7 ; v1(7846.2,7138.7) 7866.2,7138.7 ; v1(7846.2,7923.7) 7866.2,7923.7 ; v1(7846.2,8708.7) 7866.2,8708.7 ; v1(7846.2,9228.7) 7866.2,9228.7 ; v1(7866.2,9398.7) 7866.2,9228.7 ; v1(7878.6,5162.6) 7877.1,5164.1 7877.1,5257 7882.6,5262.5 7882.6,5277.2 7877.1,5282.6 7877.1,5288.7 7866.2,5299.7 7866.2,5833.7 ; 7866.2,5833.7 7866.2,6618.7 ; 7866.2,6618.7 7866.2,7138.7 ; 7866.2,7138.7 7866.2,7923.7 ; 7866.2,7923.7 7866.2,8708.7 ; 7866.2,8708.7 7866.2,9228.7
  Bottom Layer w5.9: v1(7878.6,5162.6) 7885.3,5155.9 R3$CBB19.2@7885.3,5105.4
  Bottom Layer w7.9: R3$CBB19.2@7885.3,5105.4 7955.4,5105.4 U3$CBB19.2@7960.6,5110.6
$1I36\COL+2: Q5$CBB19/CBB7.2 Q5$CBB19/CBB8.2 Q5$CBB19/CBB9.2 Q5$CBB19/CBB10.2 Q5$CBB19/CBB11.2 Q5$CBB19/CBB12.2 R5$CBB19.2 U3$CBB19.9 | length 4579.8
  Top Layer w7.9: Q5$CBB19/CBB12.2@8337.5,5808.2 8354.9,5825.6 v1(8354.9,5833.7) ; Q5$CBB19/CBB11.2@8337.5,6593.2 8354.9,6610.6 v1(8354.9,6618.7) ; Q5$CBB19/CBB10.2@8337.5,7113.2 8354.9,7130.6 v1(8354.9,7138.7) ; Q5$CBB19/CBB9.2@8337.5,7898.2 8354.9,7915.6 v1(8354.9,7923.7) ; Q5$CBB19/CBB8.2@8337.5,8683.2 8354.9,8700.6 v1(8354.9,8708.7) ; Q5$CBB19/CBB7.2@8337.5,9203.2 8354.9,9220.6 v1(8354.9,9228.7)
  Inner4 w7.9: v1(8299,5313.3) 8337.9,5313.3 8374.9,5350.3 8374.9,5833.7 ; v1(8354.9,5833.7) 8374.9,5833.7 ; v1(8354.9,6618.7) 8374.9,6618.7 ; v1(8354.9,7138.7) 8374.9,7138.7 ; v1(8354.9,7923.7) 8374.9,7923.7 ; v1(8354.9,8708.7) 8374.9,8708.7 ; v1(8354.9,9228.7) 8374.9,9228.7 ; v1(8374.9,9398.7) 8374.9,9228.7 ; 8374.9,5833.7 8374.9,6618.7 ; 8374.9,6618.7 8374.9,7138.7 ; 8374.9,7138.7 8374.9,7923.7 ; 8374.9,7923.7 8374.9,8708.7 ; 8374.9,8708.7 8374.9,9228.7
  Bottom Layer w7.9: U3$CBB19.9@8178.6,5310.6 8244.5,5310.6 R5$CBB19.2@8250.3,5316.3
  Bottom Layer w11.8: R5$CBB19.2@8250.3,5316.3 8296,5316.3 v1(8299,5313.3)
$1I36\COL+3: Q5$CBB19/CBB13.2 Q5$CBB19/CBB14.2 Q5$CBB19/CBB15.2 Q5$CBB19/CBB16.2 Q5$CBB19/CBB17.2 Q5$CBB19/CBB18.2 R7$CBB19.2 U4$CBB19.2 | length 4703.5
  Top Layer w7.9: Q5$CBB19/CBB18.2@8846.2,5808.1 8863.6,5825.5 v1(8863.6,5833.7) ; Q5$CBB19/CBB17.2@8846.2,6593.1 8863.6,6610.5 v1(8863.6,6618.7) ; Q5$CBB19/CBB16.2@8846.2,7113.1 8863.6,7130.5 v1(8863.6,7138.7) ; Q5$CBB19/CBB15.2@8846.2,7898.1 8863.6,7915.5 v1(8863.6,7923.7) ; Q5$CBB19/CBB14.2@8846.2,8683.1 8863.6,8700.5 v1(8863.6,8708.7) ; Q5$CBB19/CBB13.2@8846.2,9203.1 8863.6,9220.5 v1(8863.6,9228.7)
  Inner4 w7.9: v1(8863.6,5833.7) 8883.6,5833.7 ; v1(8863.6,6618.7) 8883.6,6618.7 ; v1(8863.6,7138.7) 8883.6,7138.7 ; v1(8863.6,7923.7) 8883.6,7923.7 ; v1(8863.6,8708.7) 8883.6,8708.7 ; v1(8863.6,9228.7) 8883.6,9228.7 ; v1(8883.6,9398.7) 8883.6,9228.7 ; v1(8912,5174.7) 8894.8,5191.9 8894.8,5273.9 8883.6,5285.1 8883.6,5833.7 ; 8883.6,5833.7 8883.6,6618.7 ; 8883.6,6618.7 8883.6,7138.7 ; 8883.6,7138.7 8883.6,7923.7 ; 8883.6,7923.7 8883.6,8708.7 ; 8883.6,8708.7 8883.6,9228.7
  Bottom Layer w7.9: R7$CBB19.2@8902.7,5105.4 8972.8,5105.4 U4$CBB19.2@8978,5110.6
  Bottom Layer w11.8: R7$CBB19.2@8902.1,5105.4 8912,5115.3 v1(8912,5174.7)
$1I36\COL+4: Q5$CBB19/CBB19.2 Q5$CBB19/CBB20.2 Q5$CBB19/CBB21.2 Q5$CBB19/CBB22.2 Q5$CBB19/CBB23.2 Q5$CBB19/CBB24.2 R9$CBB19.2 U4$CBB19.9 | length 4561.4
  Top Layer w7.9: Q5$CBB19/CBB24.2@9354.9,5808.2 9372.3,5825.6 v1(9372.3,5833.7) ; Q5$CBB19/CBB23.2@9354.9,6593.2 9372.3,6610.6 v1(9372.3,6618.7) ; Q5$CBB19/CBB22.2@9354.9,7113.2 9372.3,7130.6 v1(9372.3,7138.7) ; Q5$CBB19/CBB21.2@9354.9,7898.2 9372.3,7915.6 v1(9372.3,7923.7) ; Q5$CBB19/CBB20.2@9354.9,8683.2 9372.3,8700.6 v1(9372.3,8708.7) ; Q5$CBB19/CBB19.2@9354.9,9203.2 9372.3,9220.6 v1(9372.3,9228.7)
  Inner4 w7.9: v1(9324.6,5310.5) 9392.3,5378.1 9392.3,5833.7 ; v1(9372.3,5833.7) 9392.3,5833.7 ; v1(9372.3,6618.7) 9392.3,6618.7 ; v1(9372.3,7138.7) 9392.3,7138.7 ; v1(9372.3,7923.7) 9392.3,7923.7 ; v1(9372.3,8708.7) 9392.3,8708.7 ; v1(9372.3,9228.7) 9392.3,9228.7 ; v1(9392.3,9398.7) 9392.3,9228.7 ; 9392.3,5833.7 9392.3,6618.7 ; 9392.3,6618.7 9392.3,7138.7 ; 9392.3,7138.7 9392.3,7923.7 ; 9392.3,7923.7 9392.3,8708.7 ; 9392.3,8708.7 9392.3,9228.7
  Bottom Layer w7.9: U4$CBB19.9@9196,5310.6 9261.9,5310.6 R9$CBB19.2@9267.7,5316.3
  Bottom Layer w11.8: R9$CBB19.2@9272.1,5316.3 9318.7,5316.3 v1(9324.6,5310.5)
$1I36\COL+5: Q5$CBB19/CBB25.2 Q5$CBB19/CBB26.2 Q5$CBB19/CBB27.2 Q5$CBB19/CBB28.2 Q5$CBB19/CBB29.2 Q5$CBB19/CBB30.2 R11$CBB19.2 U5$CBB19.2 | length 4703.3
  Top Layer w7.9: Q5$CBB19/CBB30.2@9863.6,5808.2 9881,5825.6 v1(9881,5833.7) ; Q5$CBB19/CBB29.2@9863.6,6593.2 9881,6610.6 v1(9881,6618.7) ; Q5$CBB19/CBB28.2@9863.6,7113.2 9881,7130.6 v1(9881,7138.7) ; Q5$CBB19/CBB27.2@9863.6,7898.2 9881,7915.6 v1(9881,7923.7) ; Q5$CBB19/CBB26.2@9863.6,8683.2 9881,8700.6 v1(9881,8708.7) ; Q5$CBB19/CBB25.2@9863.6,9203.2 9881,9220.6 v1(9881,9228.7)
  Inner4 w7.9: v1(9881,5833.7) 9901,5833.7 ; v1(9881,6618.7) 9901,6618.7 ; v1(9881,7138.7) 9901,7138.7 ; v1(9881,7923.7) 9901,7923.7 ; v1(9881,8708.7) 9901,8708.7 ; v1(9881,9228.7) 9901,9228.7 ; v1(9901,9398.7) 9901,9228.7 ; v1(9913.3,5158.6) 9917.1,5162.4 9917.1,5258.7 9912.2,5263.7 9912.2,5272 9901,5283.3 9901,5833.7 ; 9901,5833.7 9901,6618.7 ; 9901,6618.7 9901,7138.7 ; 9901,7138.7 9901,7923.7 ; 9901,7923.7 9901,8708.7 ; 9901,8708.7 9901,9228.7
  Bottom Layer w7.9: R11$CBB19.2@9920.1,5105.4 R11$CBB19.2@9922.1,5105.4 9990.2,5105.4 U5$CBB19.2@9995.4,5110.6
  Bottom Layer w11.8: v1(9913.3,5158.6) 9907.9,5153.2 9907.9,5126.3 9922.1,5112.1 R11$CBB19.2@9922.1,5105.4
$1I36\COL+6: Q5$CBB19/CBB31.2 Q5$CBB19/CBB32.2 Q5$CBB19/CBB33.2 Q5$CBB19/CBB34.2 Q5$CBB19/CBB35.2 Q5$CBB19/CBB36.2 R13$CBB19.2 U5$CBB19.9 | length 4577.5
  Top Layer w7.9: Q5$CBB19/CBB36.2@10372.3,5808.2 10389.7,5825.6 v1(10389.7,5833.7) ; Q5$CBB19/CBB35.2@10372.3,6593.2 10389.7,6610.6 v1(10389.7,6618.7) ; Q5$CBB19/CBB34.2@10372.3,7113.2 10389.7,7130.6 v1(10389.7,7138.7) ; Q5$CBB19/CBB33.2@10372.3,7898.2 10389.7,7915.6 v1(10389.7,7923.7) ; Q5$CBB19/CBB32.2@10372.3,8683.2 10389.7,8700.6 v1(10389.7,8708.7) ; Q5$CBB19/CBB31.2@10372.3,9203.2 10389.7,9220.6 v1(10389.7,9228.7)
  Inner4 w7.9: v1(10338.9,5309.4) 10362.8,5309.4 10409.7,5356.3 10409.7,5833.7 ; v1(10389.7,5833.7) 10409.7,5833.7 ; v1(10389.7,6618.7) 10409.7,6618.7 ; v1(10389.7,7138.7) 10409.7,7138.7 ; v1(10389.7,7923.7) 10409.7,7923.7 ; v1(10389.7,8708.7) 10409.7,8708.7 ; v1(10389.7,9228.7) 10409.7,9228.7 ; v1(10409.7,9398.7) 10409.7,9228.7 ; 10409.7,5833.7 10409.7,6618.7 ; 10409.7,6618.7 10409.7,7138.7 ; 10409.7,7138.7 10409.7,7923.7 ; 10409.7,7923.7 10409.7,8708.7 ; 10409.7,8708.7 10409.7,9228.7
  Bottom Layer w7.9: U5$CBB19.9@10213.4,5310.6 10279.3,5310.6 R13$CBB19.2@10285.1,5316.3
  Bottom Layer w11.8: R13$CBB19.2@10287.1,5316.3 10331.9,5316.3 v1(10338.9,5309.4)
$1I36\COL-1: Q8$CBB19/CBB1.2 Q8$CBB19/CBB2.2 Q8$CBB19/CBB3.2 Q8$CBB19/CBB4.2 Q8$CBB19/CBB5.2 Q8$CBB19/CBB6.2 R4$CBB19.2 U3$CBB19.6 | length 4279.2
  Inner4 w7.9: v1(7822.3,9398.7) v1(7822.3,9288.4) v1(7822.3,8768.4) v1(7822.3,7983.4) v1(7822.3,7198.4) v1(7822.3,6678.4) v1(7822.3,5893.4) 7822.3,5312.3 v1(7864.8,5269.8)
  Bottom Layer w7.9: v1(7864.8,5269.8) 7885.3,5290.3 R4$CBB19.2@7885.3,5316.3 7891,5310.6 U3$CBB19.6@7960.6,5310.6
$1I36\COL-2: Q8$CBB19/CBB7.2 Q8$CBB19/CBB8.2 Q8$CBB19/CBB9.2 Q8$CBB19/CBB10.2 Q8$CBB19/CBB11.2 Q8$CBB19/CBB12.2 R6$CBB19.2 U3$CBB19.13 | length 4400.6
  Inner4 w7.9: v1(8252.1,5160.6) 8252.1,5202.8 8279.5,5230.2 8279.5,5327.1 8331,5378.5 v1(8331,5893.4) v1(8331,6678.4) v1(8331,7198.4) v1(8331,7983.4) v1(8331,8768.4) v1(8331,9288.4) v1(8331,9398.7)
  Bottom Layer w7.9: U3$CBB19.13@8178.6,5110.6 8245.1,5110.6 R6$CBB19.2@8250.3,5105.4
  Bottom Layer w11.8: R6$CBB19.2@8250.3,5105.4 8252.1,5107.3 v1(8252.1,5160.6)
$1I36\COL-3: Q8$CBB19/CBB13.2 Q8$CBB19/CBB14.2 Q8$CBB19/CBB15.2 Q8$CBB19/CBB16.2 Q8$CBB19/CBB17.2 Q8$CBB19/CBB18.2 R8$CBB19.2 U4$CBB19.6 | length 4289
  Inner4 w7.9: v1(8839.7,9398.7) v1(8839.7,9288.4) v1(8839.7,8768.4) v1(8839.7,7983.4) v1(8839.7,7198.4) v1(8839.7,6678.4) v1(8839.7,5893.4) 8839.7,5302 8850.1,5291.6 8856.1,5291.6 8866.5,5281.2 8866.5,5277.1 v1(8877,5266.5)
  Bottom Layer w7.9: R8$CBB19.2@8902.7,5316.3 8908.4,5310.6 U4$CBB19.6@8978,5310.6
  Bottom Layer w11.8: v1(8877,5266.5) 8902.1,5291.7 R8$CBB19.2@8902.1,5316.3
$1I36\COL-4: Q8$CBB19/CBB19.2 Q8$CBB19/CBB20.2 Q8$CBB19/CBB21.2 Q8$CBB19/CBB22.2 Q8$CBB19/CBB23.2 Q8$CBB19/CBB24.2 R10$CBB19.2 U4$CBB19.13 | length 4443.6
  Inner4 w7.9: v1(9317.9,5110.4) 9317.9,5154.5 9332.1,5168.7 9332.1,5222.2 9306.8,5247.5 9306.8,5352.4 9348.4,5394 v1(9348.4,5893.4) v1(9348.4,6678.4) v1(9348.4,7198.4) v1(9348.4,7983.4) v1(9348.4,8768.4) v1(9348.4,9288.4) v1(9348.4,9398.7)
  Bottom Layer w7.9: U4$CBB19.13@9196,5110.6 9262.5,5110.6 R10$CBB19.2@9267.7,5105.4
  Bottom Layer w11.8: R10$CBB19.2@9272.1,5105.4 9312.9,5105.4 v1(9317.9,5110.4)
$1I36\COL-5: Q8$CBB19/CBB25.2 Q8$CBB19/CBB26.2 Q8$CBB19/CBB27.2 Q8$CBB19/CBB28.2 Q8$CBB19/CBB29.2 Q8$CBB19/CBB30.2 R12$CBB19.2 U5$CBB19.6 | length 4291.2
  Inner4 w7.9: v1(9857.1,9398.7) v1(9857.1,9288.4) v1(9857.1,8768.4) v1(9857.1,7983.4) v1(9857.1,7198.4) v1(9857.1,6678.4) v1(9857.1,5893.4) 9857.1,5302 9862.6,5296.5 9864.3,5296.5 9874.7,5286 9874.7,5284.4 v1(9894.4,5264.7)
  Bottom Layer w7.9: R12$CBB19.2@9920.1,5316.3 9922.1,5314.3 9925.8,5310.6 U5$CBB19.6@9995.4,5310.6
  Bottom Layer w11.8: v1(9894.4,5264.7) 9922.1,5292.4 9922.1,5314.3 R12$CBB19.2@9922.1,5316.3
$1I36\COL-6: Q8$CBB19/CBB31.2 Q8$CBB19/CBB32.2 Q8$CBB19/CBB33.2 Q8$CBB19/CBB34.2 Q8$CBB19/CBB35.2 Q8$CBB19/CBB36.2 R14$CBB19.2 U5$CBB19.13 | length 4461
  Inner4 w7.9: v1(10338.9,5112.3) 10339.9,5113.3 10339.9,5233.8 10313.5,5260.2 10313.5,5309.2 10331.5,5327.2 10346.3,5327.2 10348.4,5325 10365.8,5342.4 v1(10365.8,5893.4) v1(10365.8,6678.4) v1(10365.8,7198.4) v1(10365.8,7983.4) v1(10365.8,8768.4) v1(10365.8,9288.4) v1(10365.8,9398.7)
  Bottom Layer w7.9: U5$CBB19.13@10213.4,5110.6 10279.9,5110.6 R14$CBB19.2@10285.1,5105.4
  Bottom Layer w11.8: R14$CBB19.2@10287.1,5105.4 10332,5105.4 v1(10338.9,5112.3)
$1I38\$1I15\$1N1: R9$CBB20/CBB1.1 U6$CBB20/CBB1.15 | length 333.4
  Top Layer w7.9: R9$CBB20/CBB1.1@6685.7,9192.8 6802.9,9192.8 6896.1,9099.6 U6$CBB20/CBB1.15@6980.5,9099.6
$1I38\$1I15\$1N2: R8$CBB20/CBB1.1 U6$CBB20/CBB1.1 | length 77.5
  Top Layer w7.9: R8$CBB20/CBB1.1@6685.7,9147.8 6760.7,9147.8 U6$CBB20/CBB1.1@6762.5,9149.6
$1I38\$1I15\$1N3: R7$CBB20/CBB1.1 U6$CBB20/CBB1.2 | length 77.5
  Top Layer w7.9: R7$CBB20/CBB1.1@6685.7,9097.8 6760.7,9097.8 U6$CBB20/CBB1.2@6762.5,9099.6
$1I38\$1I15\$1N4: R6$CBB20/CBB1.1 U6$CBB20/CBB1.3 | length 77.5
  Top Layer w7.9: R6$CBB20/CBB1.1@6685.7,9047.8 6760.7,9047.8 U6$CBB20/CBB1.3@6762.5,9049.6
$1I38\$1I15\$1N5: R5$CBB20/CBB1.1 U6$CBB20/CBB1.4 | length 77.5
  Top Layer w7.9: R5$CBB20/CBB1.1@6685.7,8997.8 6760.7,8997.8 U6$CBB20/CBB1.4@6762.5,8999.6
$1I38\$1I15\$1N6: R4$CBB20/CBB1.1 U6$CBB20/CBB1.5 | length 77.5
  Top Layer w7.9: R4$CBB20/CBB1.1@6685.7,8947.8 6760.7,8947.8 U6$CBB20/CBB1.5@6762.5,8949.6
$1I38\$1I15\$1N7: R3$CBB20/CBB1.1 U6$CBB20/CBB1.6 | length 77.5
  Top Layer w7.9: R3$CBB20/CBB1.1@6685.7,8897.8 6760.7,8897.8 U6$CBB20/CBB1.6@6762.5,8899.6
$1I38\$1I15\$1N8: R1$CBB20/CBB1.1 U6$CBB20/CBB1.7 | length 77.5
  Top Layer w7.9: R1$CBB20/CBB1.1@6685.7,8847.8 6760.7,8847.8 U6$CBB20/CBB1.7@6762.5,8849.6
$1I38\$1I15\$1N11: R2$CBB20/CBB1.1 R8$CBB20/CBB1.2 R10$CBB20/CBB1.2 | length 99.7
  Top Layer w7.9: R2$CBB20/CBB1.1@6558.6,9135.8 6602.7,9135.8 R10$CBB20/CBB1.2@6603.6,9134.9 6604.8,9133.7 6617,9133.7 6631.1,9147.8 R8$CBB20/CBB1.2@6651.6,9147.8
$1I38\$1I15\$1N12: R6$CBB20/CBB1.2 R11$CBB20/CBB1.1 R12$CBB20/CBB1.2 | length 102.8
  Top Layer w7.9: R11$CBB20/CBB1.1@6558.6,9055.8 6574.9,9055.8 6590.8,9039.9 R12$CBB20/CBB1.2@6603.6,9039.9 6623.1,9039.9 6631.1,9047.8 R6$CBB20/CBB1.2@6651.6,9047.8
$1I38\$1I15\$1N13: R7$CBB20/CBB1.2 R10$CBB20/CBB1.1 R11$CBB20/CBB1.2 | length 98.8
  Top Layer w7.9: R11$CBB20/CBB1.2@6558.6,9089.9 6568.1,9089.9 6579,9100.8 R10$CBB20/CBB1.1@6603.6,9100.8 6648.6,9100.8 R7$CBB20/CBB1.2@6651.6,9097.8
$1I38\$1I15\$1N14: R4$CBB20/CBB1.2 R13$CBB20/CBB1.1 R14$CBB20/CBB1.2 | length 102.8
  Top Layer w7.9: R13$CBB20/CBB1.1@6558.6,8955.8 6574.9,8955.8 6590.8,8939.9 R14$CBB20/CBB1.2@6603.6,8939.9 6618.1,8939.9 6626.1,8947.8 R4$CBB20/CBB1.2@6651.6,8947.8
$1I38\$1I15\$1N15: R5$CBB20/CBB1.2 R12$CBB20/CBB1.1 R13$CBB20/CBB1.2 | length 102.9
  Top Layer w7.9: R13$CBB20/CBB1.2@6558.6,8989.9 6573.1,8989.9 6589,9005.8 R12$CBB20/CBB1.1@6603.6,9005.8 6619.9,9005.8 6627.9,8997.8 R5$CBB20/CBB1.2@6651.6,8997.8
$1I38\$1I15\$1N16: R1$CBB20/CBB1.2 R15$CBB20/CBB1.1 R16$CBB20/CBB1.2 | length 143.4
  Top Layer w7.9: R15$CBB20/CBB1.1@6558.6,8860.8 6589.9,8860.8 6602.9,8847.8 R1$CBB20/CBB1.2@6651.6,8847.8 R16$CBB20/CBB1.2@6651.6,8802.8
